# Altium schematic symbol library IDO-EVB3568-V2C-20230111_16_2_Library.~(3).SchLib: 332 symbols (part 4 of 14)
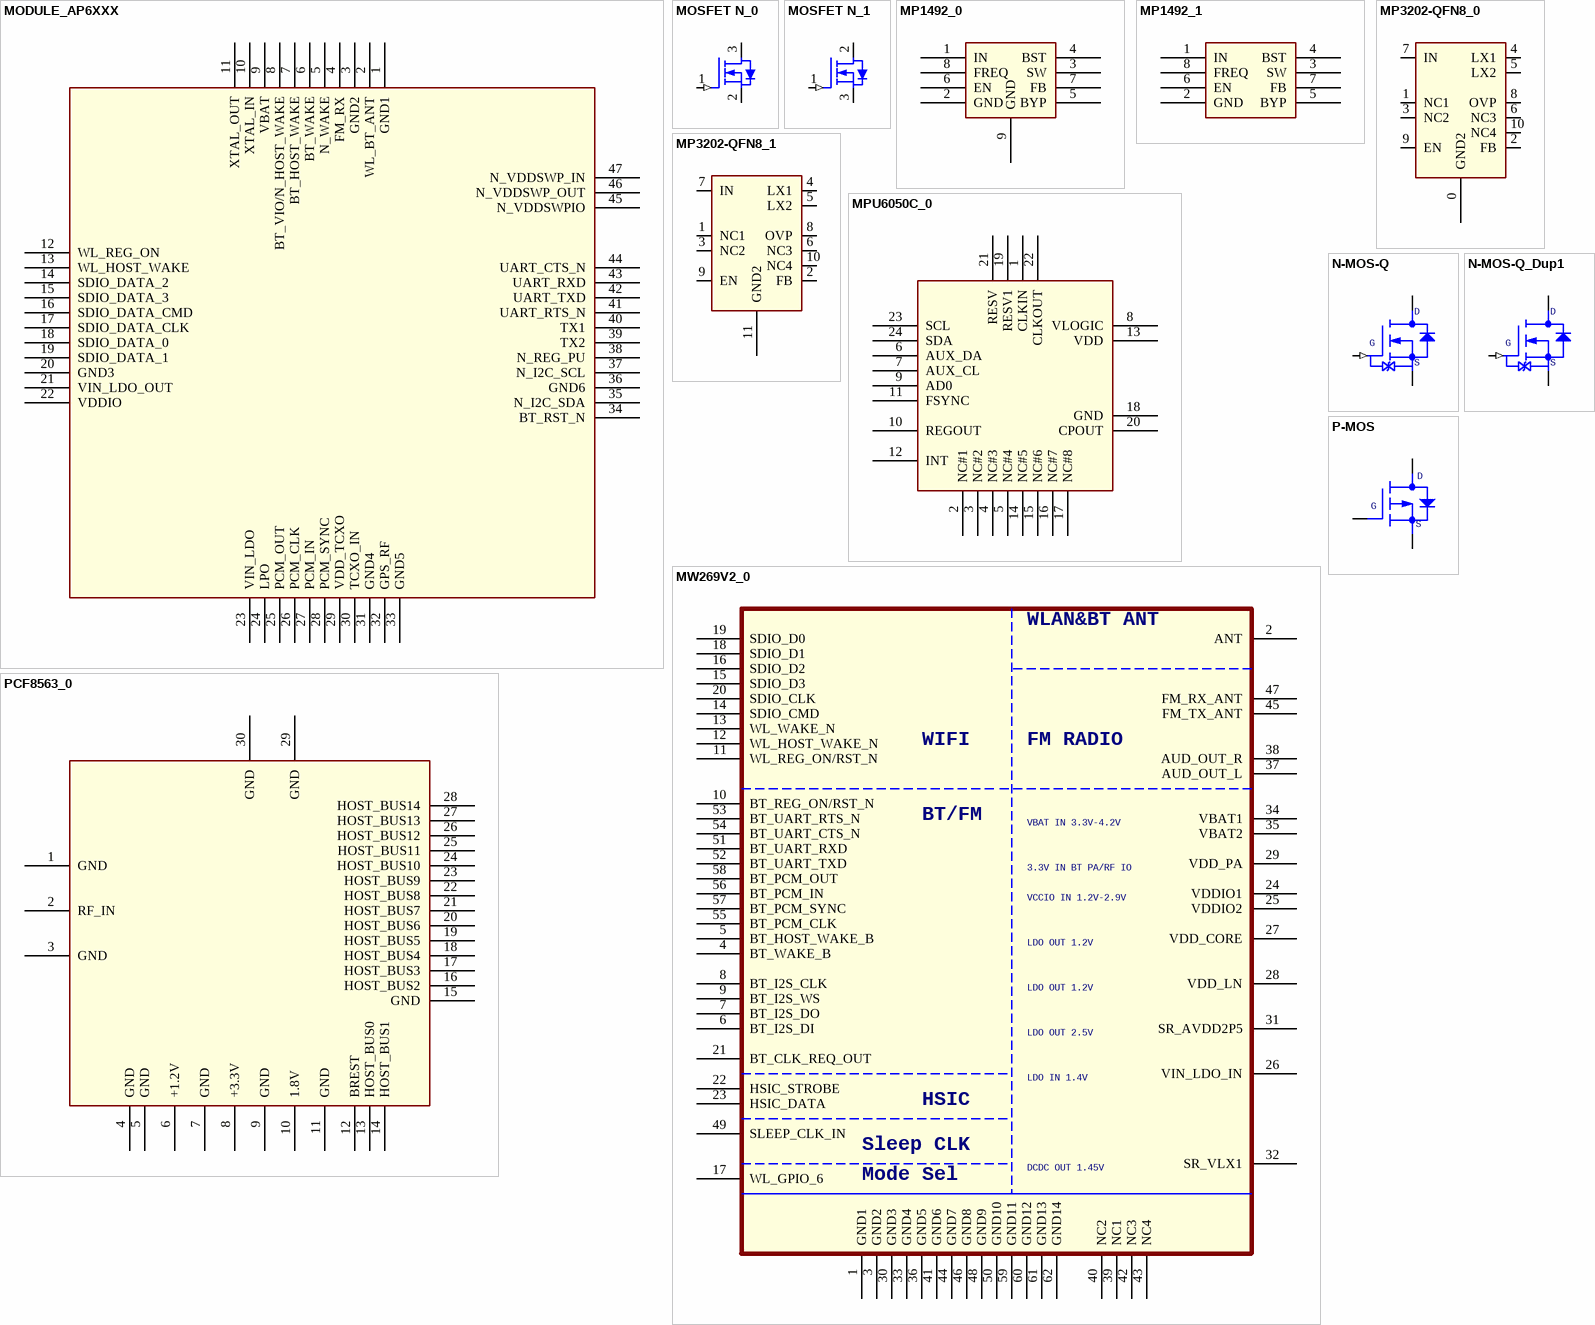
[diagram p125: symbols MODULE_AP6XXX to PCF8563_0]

## PCF8563_0
designator U?
Altium-Right: 240; Altium-Bottom: 230
footprint SOP-8
pins: 1 GND, 2 RF_IN, 3 GND, 4 GND, 5 GND, 6 +1.2V, 7 GND, 8 +3.3V, 9 GND, 10 1.8V, 11 GND, 12 BREST, 13 HOST_BUS0, 14 HOST_BUS1, 15 GND, 16 HOST_BUS2, 17 HOST_BUS3, 18 HOST_BUS4, 19 HOST_BUS5, 20 HOST_BUS6, 21 HOST_BUS7, 22 HOST_BUS8, 23 HOST_BUS9, 24 HOST_BUS10, 25 HOST_BUS11, 26 HOST_BUS12, 27 HOST_BUS13, 28 HOST_BUS14, 29 GND, 30 GND
1 alternate drawing of the same symbol

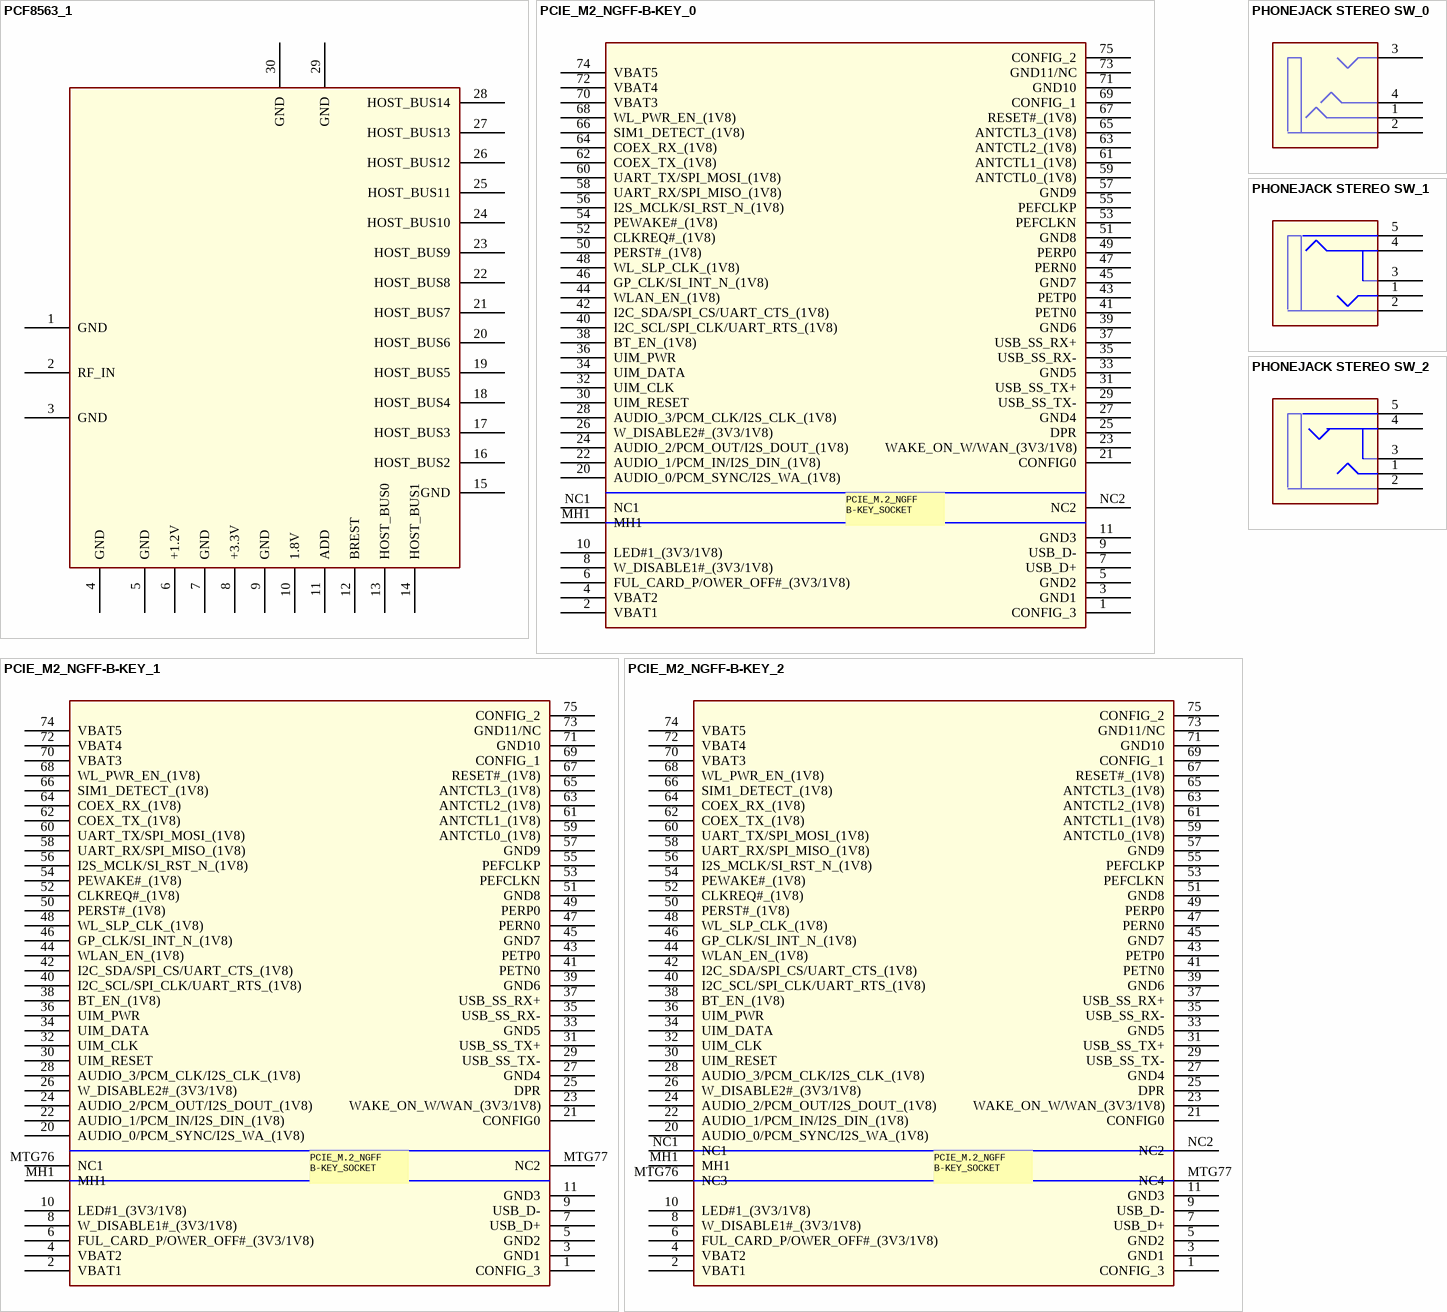
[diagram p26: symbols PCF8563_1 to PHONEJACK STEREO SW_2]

## PCF8563_1
designator U?
Altium-Right: 260; Altium-Bottom: 320
footprint SOP-8
pins: 1 GND, 2 RF_IN, 3 GND, 4 GND, 5 GND, 6 +1.2V, 7 GND, 8 +3.3V, 9 GND, 10 1.8V, 11 ADD, 12 BREST, 13 HOST_BUS0, 14 HOST_BUS1, 15 GND, 16 HOST_BUS2, 17 HOST_BUS3, 18 HOST_BUS4, 19 HOST_BUS5, 20 HOST_BUS6, 21 HOST_BUS7, 22 HOST_BUS8, 23 HOST_BUS9, 24 HOST_BUS10, 25 HOST_BUS11, 26 HOST_BUS12, 27 HOST_BUS13, 28 HOST_BUS14, 29 GND, 30 GND
1 alternate drawing of the same symbol

## PCIE_M2_NGFF-B-KEY_0
designator U?
Altium-Right: 320; Altium-Bottom: 390
pins: 1 CONFIG_3, 2 VBAT1, 3 GND1, 4 VBAT2, 5 GND2, 6 FUL_CARD_P/OWER_OFF#_(3V3/1V8), 7 USB_D+, 8 W_DISABLE1#_(3V3/1V8), 9 USB_D-, 10 LED#1_(3V3/1V8), 11 GND3, 20 AUDIO_0/PCM_SYNC/I2S_WA_(1V8), 21 CONFIG0, 22 AUDIO_1/PCM_IN/I2S_DIN_(1V8), 23 WAKE_ON_W/WAN_(3V3/1V8), 24 AUDIO_2/PCM_OUT/I2S_DOUT_(1V8), 25 DPR, 26 W_DISABLE2#_(3V3/1V8), 27 GND4, 28 AUDIO_3/PCM_CLK/I2S_CLK_(1V8), 29 USB_SS_TX-, 30 UIM_RESET, 31 USB_SS_TX+, 32 UIM_CLK, 33 GND5, 34 UIM_DATA, 35 USB_SS_RX-, 36 UIM_PWR, 37 USB_SS_RX+, 38 BT_EN_(1V8), 39 GND6, 40 I2C_SCL/SPI_CLK/UART_RTS_(1V8), 41 PETN0, 42 I2C_SDA/SPI_CS/UART_CTS_(1V8), 43 PETP0, 44 WLAN_EN_(1V8), 45 GND7, 46 GP_CLK/SI_INT_N_(1V8), 47 PERN0, 48 WL_SLP_CLK_(1V8), 49 PERP0, 50 PERST#_(1V8), 51 GND8, 52 CLKREQ#_(1V8), 53 PEFCLKN, 54 PEWAKE#_(1V8), 55 PEFCLKP, 56 I2S_MCLK/SI_RST_N_(1V8), 57 GND9, 58 UART_RX/SPI_MISO_(1V8), 59 ANTCTL0_(1V8), 60 UART_TX/SPI_MOSI_(1V8), 61 ANTCTL1_(1V8), 62 COEX_TX_(1V8), 63 ANTCTL2_(1V8), 64 COEX_RX_(1V8), 65 ANTCTL3_(1V8), 66 SIM1_DETECT_(1V8), 67 RESET#_(1V8), 68 WL_PWR_EN_(1V8), 69 CONFIG_1, 70 VBAT3, 71 GND10, 72 VBAT4, 73 GND11/NC, 74 VBAT5, 75 CONFIG_2, MH1, NC1, NC2

## PCIE_M2_NGFF-B-KEY_1
designator U?
Altium-Right: 320; Altium-Bottom: 390
pins: 1 CONFIG_3, 2 VBAT1, 3 GND1, 4 VBAT2, 5 GND2, 6 FUL_CARD_P/OWER_OFF#_(3V3/1V8), 7 USB_D+, 8 W_DISABLE1#_(3V3/1V8), 9 USB_D-, 10 LED#1_(3V3/1V8), 11 GND3, 20 AUDIO_0/PCM_SYNC/I2S_WA_(1V8), 21 CONFIG0, 22 AUDIO_1/PCM_IN/I2S_DIN_(1V8), 23 WAKE_ON_W/WAN_(3V3/1V8), 24 AUDIO_2/PCM_OUT/I2S_DOUT_(1V8), 25 DPR, 26 W_DISABLE2#_(3V3/1V8), 27 GND4, 28 AUDIO_3/PCM_CLK/I2S_CLK_(1V8), 29 USB_SS_TX-, 30 UIM_RESET, 31 USB_SS_TX+, 32 UIM_CLK, 33 GND5, 34 UIM_DATA, 35 USB_SS_RX-, 36 UIM_PWR, 37 USB_SS_RX+, 38 BT_EN_(1V8), 39 GND6, 40 I2C_SCL/SPI_CLK/UART_RTS_(1V8), 41 PETN0, 42 I2C_SDA/SPI_CS/UART_CTS_(1V8), 43 PETP0, 44 WLAN_EN_(1V8), 45 GND7, 46 GP_CLK/SI_INT_N_(1V8), 47 PERN0, 48 WL_SLP_CLK_(1V8), 49 PERP0, 50 PERST#_(1V8), 51 GND8, 52 CLKREQ#_(1V8), 53 PEFCLKN, 54 PEWAKE#_(1V8), 55 PEFCLKP, 56 I2S_MCLK/SI_RST_N_(1V8), 57 GND9, 58 UART_RX/SPI_MISO_(1V8), 59 ANTCTL0_(1V8), 60 UART_TX/SPI_MOSI_(1V8), 61 ANTCTL1_(1V8), 62 COEX_TX_(1V8), 63 ANTCTL2_(1V8), 64 COEX_RX_(1V8), 65 ANTCTL3_(1V8), 66 SIM1_DETECT_(1V8), 67 RESET#_(1V8), 68 WL_PWR_EN_(1V8), 69 CONFIG_1, 70 VBAT3, 71 GND10, 72 VBAT4, 73 GND11/NC, 74 VBAT5, 75 CONFIG_2, MH1, MTG76 NC1, MTG77 NC2

## PCIE_M2_NGFF-B-KEY_2
designator U?
Altium-Right: 320; Altium-Bottom: 390
pins: 1 CONFIG_3, 2 VBAT1, 3 GND1, 4 VBAT2, 5 GND2, 6 FUL_CARD_P/OWER_OFF#_(3V3/1V8), 7 USB_D+, 8 W_DISABLE1#_(3V3/1V8), 9 USB_D-, 10 LED#1_(3V3/1V8), 11 GND3, 20 AUDIO_0/PCM_SYNC/I2S_WA_(1V8), 21 CONFIG0, 22 AUDIO_1/PCM_IN/I2S_DIN_(1V8), 23 WAKE_ON_W/WAN_(3V3/1V8), 24 AUDIO_2/PCM_OUT/I2S_DOUT_(1V8), 25 DPR, 26 W_DISABLE2#_(3V3/1V8), 27 GND4, 28 AUDIO_3/PCM_CLK/I2S_CLK_(1V8), 29 USB_SS_TX-, 30 UIM_RESET, 31 USB_SS_TX+, 32 UIM_CLK, 33 GND5, 34 UIM_DATA, 35 USB_SS_RX-, 36 UIM_PWR, 37 USB_SS_RX+, 38 BT_EN_(1V8), 39 GND6, 40 I2C_SCL/SPI_CLK/UART_RTS_(1V8), 41 PETN0, 42 I2C_SDA/SPI_CS/UART_CTS_(1V8), 43 PETP0, 44 WLAN_EN_(1V8), 45 GND7, 46 GP_CLK/SI_INT_N_(1V8), 47 PERN0, 48 WL_SLP_CLK_(1V8), 49 PERP0, 50 PERST#_(1V8), 51 GND8, 52 CLKREQ#_(1V8), 53 PEFCLKN, 54 PEWAKE#_(1V8), 55 PEFCLKP, 56 I2S_MCLK/SI_RST_N_(1V8), 57 GND9, 58 UART_RX/SPI_MISO_(1V8), 59 ANTCTL0_(1V8), 60 UART_TX/SPI_MOSI_(1V8), 61 ANTCTL1_(1V8), 62 COEX_TX_(1V8), 63 ANTCTL2_(1V8), 64 COEX_RX_(1V8), 65 ANTCTL3_(1V8), 66 SIM1_DETECT_(1V8), 67 RESET#_(1V8), 68 WL_PWR_EN_(1V8), 69 CONFIG_1, 70 VBAT3, 71 GND10, 72 VBAT4, 73 GND11/NC, 74 VBAT5, 75 CONFIG_2, MH1, MTG76 NC3, MTG77 NC4, NC1, NC2

## PHONEJACK STEREO SW_0
designator J?
Altium-Right: 70
pins: 1 HP, 2 COM, 3 L, 4 R

## PHONEJACK STEREO SW_1
designator J?
Altium-Right: 70
footprint PHONE-ST-0166MT-050
pins: 1 R, 2 COM, 3 HP, 4 L, 5

## PHONEJACK STEREO SW_2
designator J?
Altium-Right: 70
footprint PHONE-ST-0166MT-050
pins: 1 R, 2 COM, 3 HP, 4 L, 5

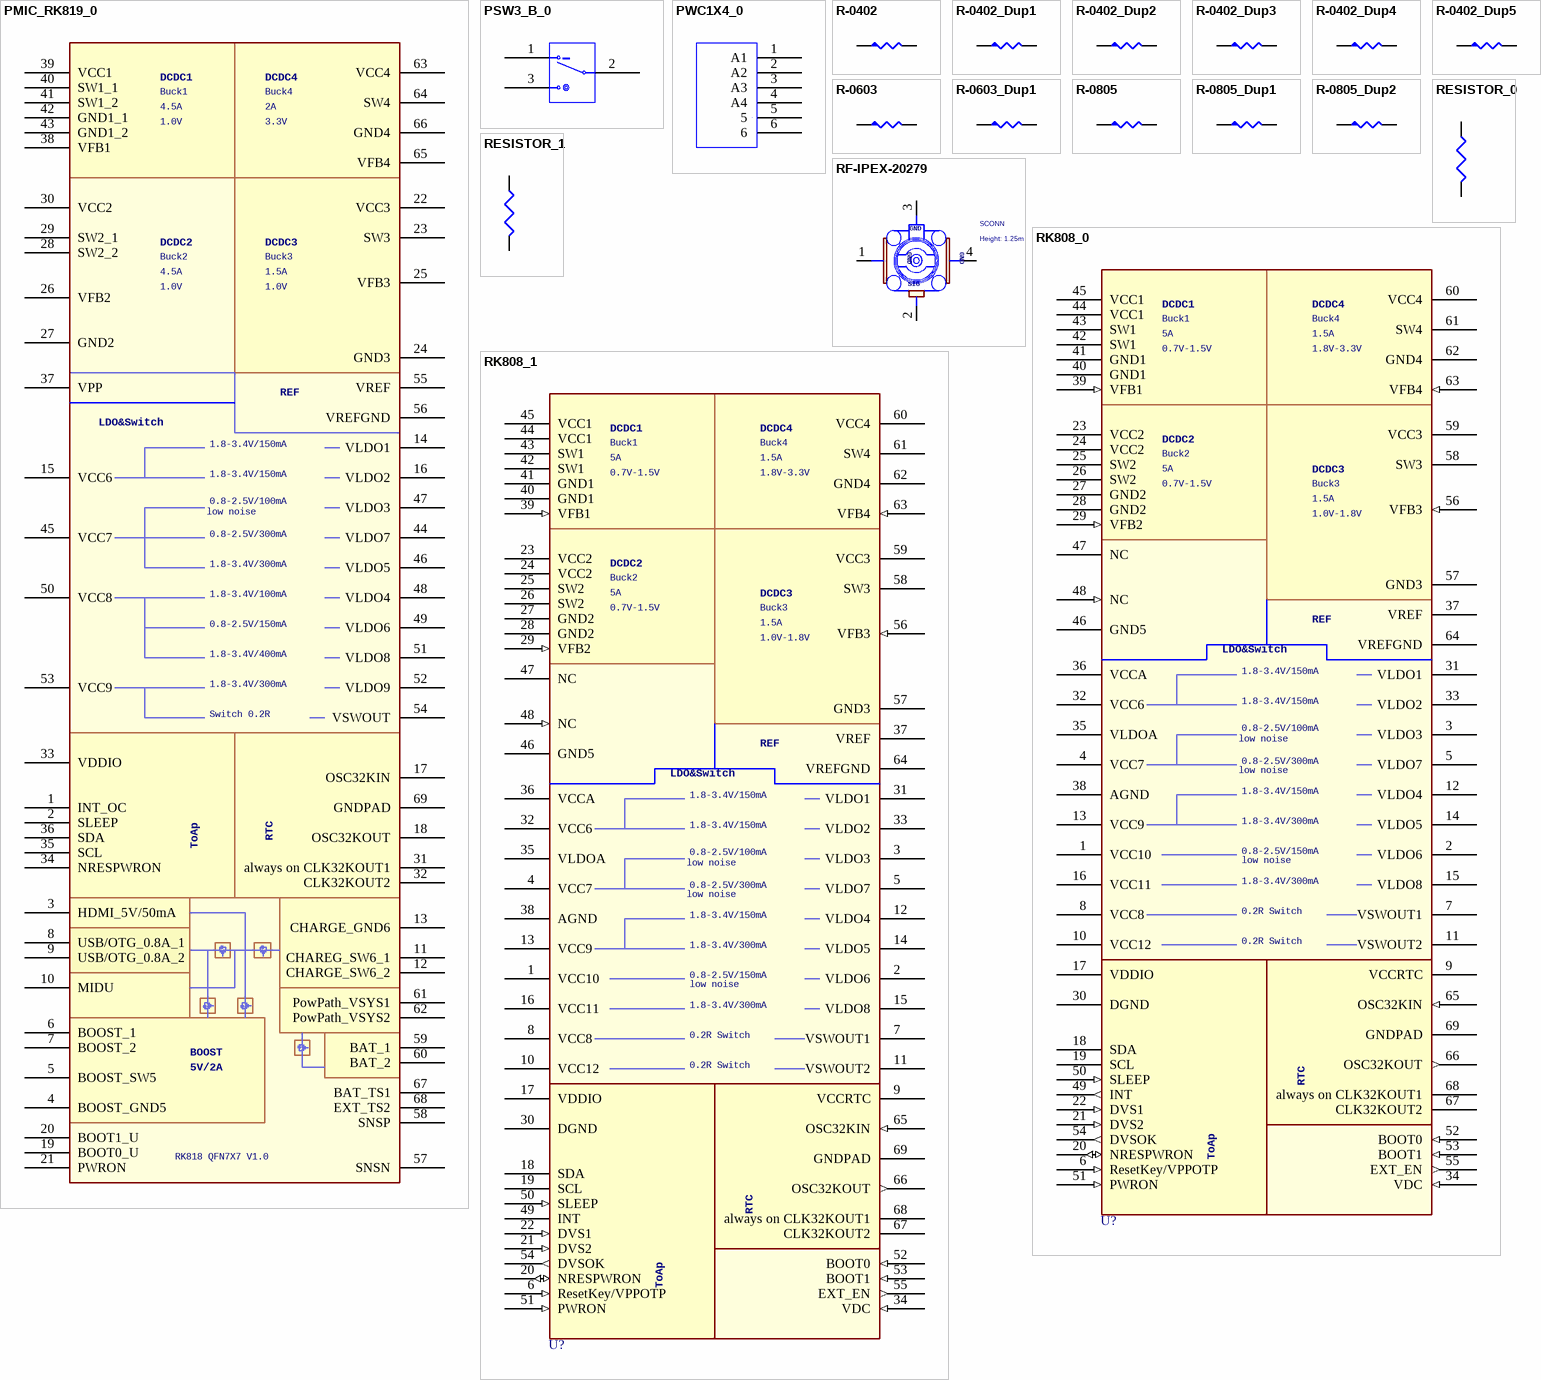
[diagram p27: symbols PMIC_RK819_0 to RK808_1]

## PMIC_RK819_0
designator U?
Altium-Right: 220; Altium-Bottom: 760
footprint QFN68
pins: 1 INT_OC, 2 SLEEP, 3 HDMI_5V/50mA, 4 BOOST_GND5, 5 BOOST_SW5, 6 BOOST_1, 7 BOOST_2, 8 USB/OTG_0.8A_1, 9 USB/OTG_0.8A_2, 10 MIDU, 11 CHAREG_SW6_1, 12 CHARGE_SW6_2, 13 CHARGE_GND6, 14 VLDO1, 15 VCC6, 16 VLDO2, 17 OSC32KIN, 18 OSC32KOUT, 19 BOOT0_U, 20 BOOT1_U, 21 PWRON, 22 VCC3, 23 SW3, 24 GND3, 25 VFB3, 26 VFB2, 27 GND2, 28 SW2_2, 29 SW2_1, 30 VCC2, 31 always on CLK32KOUT1, 32 CLK32KOUT2, 33 VDDIO, 34 NRESPWRON, 35 SCL, 36 SDA, 37 VPP, 38 VFB1, 39 VCC1, 40 SW1_1, 41 SW1_2, 42 GND1_1, 43 GND1_2, 44 VLDO7, 45 VCC7, 46 VLDO5, 47 VLDO3, 48 VLDO4, 49 VLDO6, 50 VCC8, 51 VLDO8, 52 VLDO9, 53 VCC9, 54 VSWOUT, 55 VREF, 56 VREFGND, 57 SNSN, 58 SNSP, 59 BAT_1, 60 BAT_2, 61 PowPath_VSYS1, 62 PowPath_VSYS2, 63 VCC4, 64 SW4, 65 VFB4, 66 GND4, 67 BAT_TS1, 68 EXT_TS2, 69 GNDPAD

## PSW3_B_0
designator S?, comment PSW3_B  (value not drawn)
PARTS: 1; DEVICE: BR-11C-11P6; LEVEL: STD; OriginalSymbolOrigin: (20,50); Altium-Right: 30; Altium-Bottom: 40
pins: 1 P1, 2 P2, 3 P3

## PWC1X4_0
designator J?, comment PWC1X4  (value not drawn)
PARTS: 1; DEVICE: HEAD1X4; LEVEL: STD; PKG_TYPE: 4; OriginalSymbolOrigin: (0,70); Altium-Right: 40; Altium-Bottom: 70
pins: 1 A1, 2 A2, 3 A3, 4 A4, 5, 6

## R-0402
designator R?
Altium-Right: 20
pins: 1, 2

## R-0402_Dup1
designator R?
Altium-Right: 20
pins: 1, 2

## R-0402_Dup2
designator R?
Altium-Right: 20
pins: 1, 2

## R-0402_Dup3
designator R?
Altium-Right: 20
pins: 1, 2

## R-0402_Dup4
designator R?
Altium-Right: 20
pins: 1, 2

## R-0402_Dup5
designator R?
Altium-Right: 20
pins: 1, 2

## R-0603
designator R?
Altium-Right: 20
pins: 1, 2

## R-0603_Dup1
designator R?
Altium-Right: 20
pins: 1, 2

## R-0805
designator R?
Altium-Right: 20
pins: 1, 2

## R-0805_Dup1
designator R?
Altium-Right: 20
pins: 1, 2

## R-0805_Dup2
designator R?
Altium-Right: 20
pins: 1, 2

## RESISTOR_0
designator R?
Altium-Right: 20; Altium-Bottom: 30
pins: 1, 2

## RESISTOR_1
designator R?
Altium-Right: 20; Altium-Bottom: 30
pins: 1, 2

## RF-IPEX-20279
designator IPEX?  Material: SCONN  Height: 1.25mm
SMD micro Coaxial Connector Receptacle vertial; Pack_Type: MHF-20279; Altium-Right: 60
pins: 1 GND1, 2 SIG, 3 GND2, 4 GND3

## RK808_0
designator U?  (value not drawn)
Altium-Right: 220; Altium-Bottom: 630
pins: 1 VCC10 (power), 2 VLDO6 (power), 3 VLDO3 (power), 4 VCC7 (power), 5 VLDO7 (power), 6 ResetKey/VPPOTP (in), 7 VSWOUT1 (power), 8 VCC8 (power), 9 VCCRTC (power), 10 VCC12 (power), 11 VSWOUT2 (power), 12 VLDO4 (power), 13 VCC9 (power), 14 VLDO5 (power), 15 VLDO8 (power), 16 VCC11 (power), 17 VDDIO (power), 18 SDA (oc), 19 SCL (oc), 20 NRESPWRON (io), 21 DVS2 (in), 22 DVS1 (in), 23 VCC2 (power), 24 VCC2 (power), 25 SW2 (power), 26 SW2 (power), 27 GND2 (power), 28 GND2 (power), 29 VFB2 (in), 30 DGND (power), 31 VLDO1 (power), 32 VCC6 (power), 33 VLDO2 (power), 34 VDC (in), 35 VLDOA (power), 36 VCCA (power), 37 VREF (power), 38 AGND (power), 39 VFB1 (in), 40 GND1 (power), 41 GND1 (power), 42 SW1 (power), 43 SW1 (power), 44 VCC1 (power), 45 VCC1 (power), 46 GND5 (power), 47 NC (hiz), 48 NC (in), 49 INT (out), 50 SLEEP (in), 51 PWRON (in), 52 BOOT0 (in), 53 BOOT1 (in), 54 DVSOK (out), 55 EXT_EN (out), 56 VFB3 (in), 57 GND3 (power), 58 SW3 (power), 59 VCC3 (power), 60 VCC4 (power), 61 SW4 (power), 62 GND4 (power), 63 VFB4 (in), 64 VREFGND (power), 65 OSC32KIN (in), 66 OSC32KOUT (out), 67 CLK32KOUT2 (oc), 68 always on CLK32KOUT1 (oc), 69 GNDPAD (power)

## RK808_1
designator U?  (value not drawn)
Altium-Right: 220; Altium-Bottom: 630
pins: 1 VCC10 (power), 2 VLDO6 (power), 3 VLDO3 (power), 4 VCC7 (power), 5 VLDO7 (power), 6 ResetKey/VPPOTP (in), 7 VSWOUT1 (power), 8 VCC8 (power), 9 VCCRTC (power), 10 VCC12 (power), 11 VSWOUT2 (power), 12 VLDO4 (power), 13 VCC9 (power), 14 VLDO5 (power), 15 VLDO8 (power), 16 VCC11 (power), 17 VDDIO (power), 18 SDA (oc), 19 SCL (oc), 20 NRESPWRON (io), 21 DVS2 (in), 22 DVS1 (in), 23 VCC2 (power), 24 VCC2 (power), 25 SW2 (power), 26 SW2 (power), 27 GND2 (power), 28 GND2 (power), 29 VFB2 (in), 30 DGND (power), 31 VLDO1 (power), 32 VCC6 (power), 33 VLDO2 (power), 34 VDC (in), 35 VLDOA (power), 36 VCCA (power), 37 VREF (power), 38 AGND (power), 39 VFB1 (in), 40 GND1 (power), 41 GND1 (power), 42 SW1 (power), 43 SW1 (power), 44 VCC1 (power), 45 VCC1 (power), 46 GND5 (power), 47 NC (hiz), 48 NC (in), 49 INT, 50 SLEEP (in), 51 PWRON (in), 52 BOOT0 (in), 53 BOOT1 (in), 54 DVSOK (out), 55 EXT_EN (out), 56 VFB3 (in), 57 GND3 (power), 58 SW3 (power), 59 VCC3 (power), 60 VCC4 (power), 61 SW4 (power), 62 GND4 (power), 63 VFB4 (in), 64 VREFGND (power), 65 OSC32KIN (in), 66 OSC32KOUT (out), 67 CLK32KOUT2 (oc), 68 always on CLK32KOUT1 (oc), 69 GNDPAD (power)

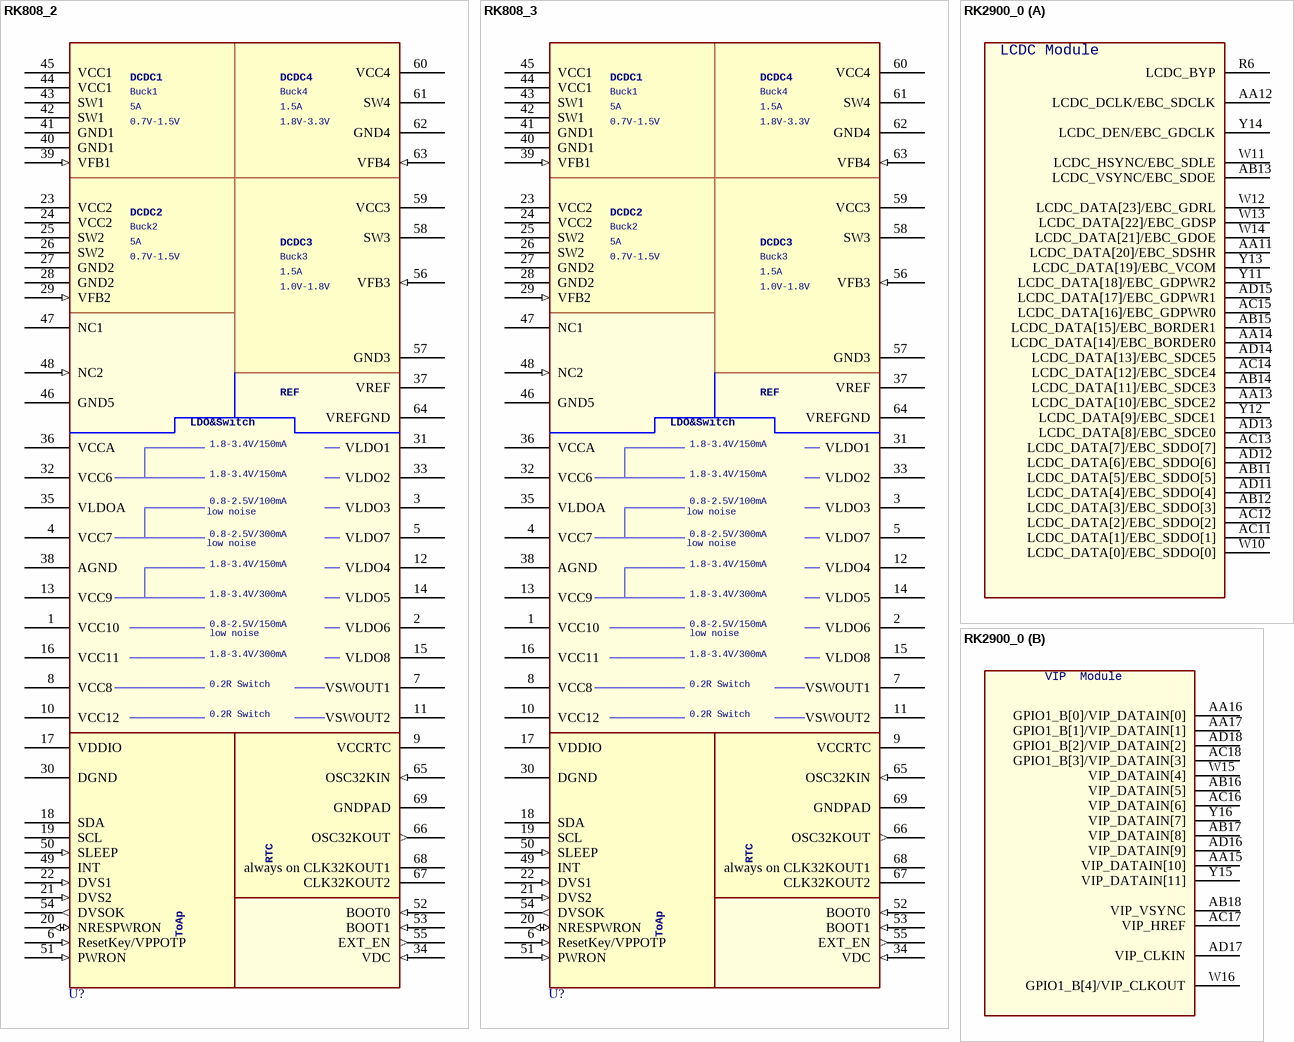
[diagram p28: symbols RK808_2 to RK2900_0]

## RK808_2
designator U?  (value not drawn)
Altium-Right: 220; Altium-Bottom: 630
pins: 1 VCC10 (power), 2 VLDO6 (power), 3 VLDO3 (power), 4 VCC7 (power), 5 VLDO7 (power), 6 ResetKey/VPPOTP (in), 7 VSWOUT1 (power), 8 VCC8 (power), 9 VCCRTC (power), 10 VCC12 (power), 11 VSWOUT2 (power), 12 VLDO4 (power), 13 VCC9 (power), 14 VLDO5 (power), 15 VLDO8 (power), 16 VCC11 (power), 17 VDDIO (power), 18 SDA (oc), 19 SCL (oc), 20 NRESPWRON (io), 21 DVS2 (in), 22 DVS1 (in), 23 VCC2 (power), 24 VCC2 (power), 25 SW2 (power), 26 SW2 (power), 27 GND2 (power), 28 GND2 (power), 29 VFB2 (in), 30 DGND (power), 31 VLDO1 (power), 32 VCC6 (power), 33 VLDO2 (power), 34 VDC (in), 35 VLDOA (power), 36 VCCA (power), 37 VREF (power), 38 AGND (power), 39 VFB1 (in), 40 GND1 (power), 41 GND1 (power), 42 SW1 (power), 43 SW1 (power), 44 VCC1 (power), 45 VCC1 (power), 46 GND5 (power), 47 NC1 (hiz), 48 NC2 (in), 49 INT, 50 SLEEP (in), 51 PWRON (in), 52 BOOT0 (in), 53 BOOT1 (in), 54 DVSOK (out), 55 EXT_EN (out), 56 VFB3 (in), 57 GND3 (power), 58 SW3 (power), 59 VCC3 (power), 60 VCC4 (power), 61 SW4 (power), 62 GND4 (power), 63 VFB4 (in), 64 VREFGND (power), 65 OSC32KIN (in), 66 OSC32KOUT (out), 67 CLK32KOUT2 (oc), 68 always on CLK32KOUT1 (oc), 69 GNDPAD (power)

## RK808_3
designator U?  (value not drawn)
Altium-Right: 220; Altium-Bottom: 630
pins: 1 VCC10 (power), 2 VLDO6 (power), 3 VLDO3 (power), 4 VCC7 (power), 5 VLDO7 (power), 6 ResetKey/VPPOTP (in), 7 VSWOUT1 (power), 8 VCC8 (power), 9 VCCRTC (power), 10 VCC12 (power), 11 VSWOUT2 (power), 12 VLDO4 (power), 13 VCC9 (power), 14 VLDO5 (power), 15 VLDO8 (power), 16 VCC11 (power), 17 VDDIO (power), 18 SDA (oc), 19 SCL (oc), 20 NRESPWRON (io), 21 DVS2 (in), 22 DVS1 (in), 23 VCC2 (power), 24 VCC2 (power), 25 SW2 (power), 26 SW2 (power), 27 GND2 (power), 28 GND2 (power), 29 VFB2 (in), 30 DGND (power), 31 VLDO1 (power), 32 VCC6 (power), 33 VLDO2 (power), 34 VDC (in), 35 VLDOA (power), 36 VCCA (power), 37 VREF (power), 38 AGND (power), 39 VFB1 (in), 40 GND1 (power), 41 GND1 (power), 42 SW1 (power), 43 SW1 (power), 44 VCC1 (power), 45 VCC1 (power), 46 GND5 (power), 47 NC1 (hiz), 48 NC2 (in), 49 INT, 50 SLEEP (in), 51 PWRON (in), 52 BOOT0 (in), 53 BOOT1 (in), 54 DVSOK (out), 55 EXT_EN (out), 56 VFB3 (in), 57 GND3 (power), 58 SW3 (power), 59 VCC3 (power), 60 VCC4 (power), 61 SW4 (power), 62 GND4 (power), 63 VFB4 (in), 64 VREFGND (power), 65 OSC32KIN (in), 66 OSC32KOUT (out), 67 CLK32KOUT2 (oc), 68 always on CLK32KOUT1 (oc), 69 GNDPAD (power)

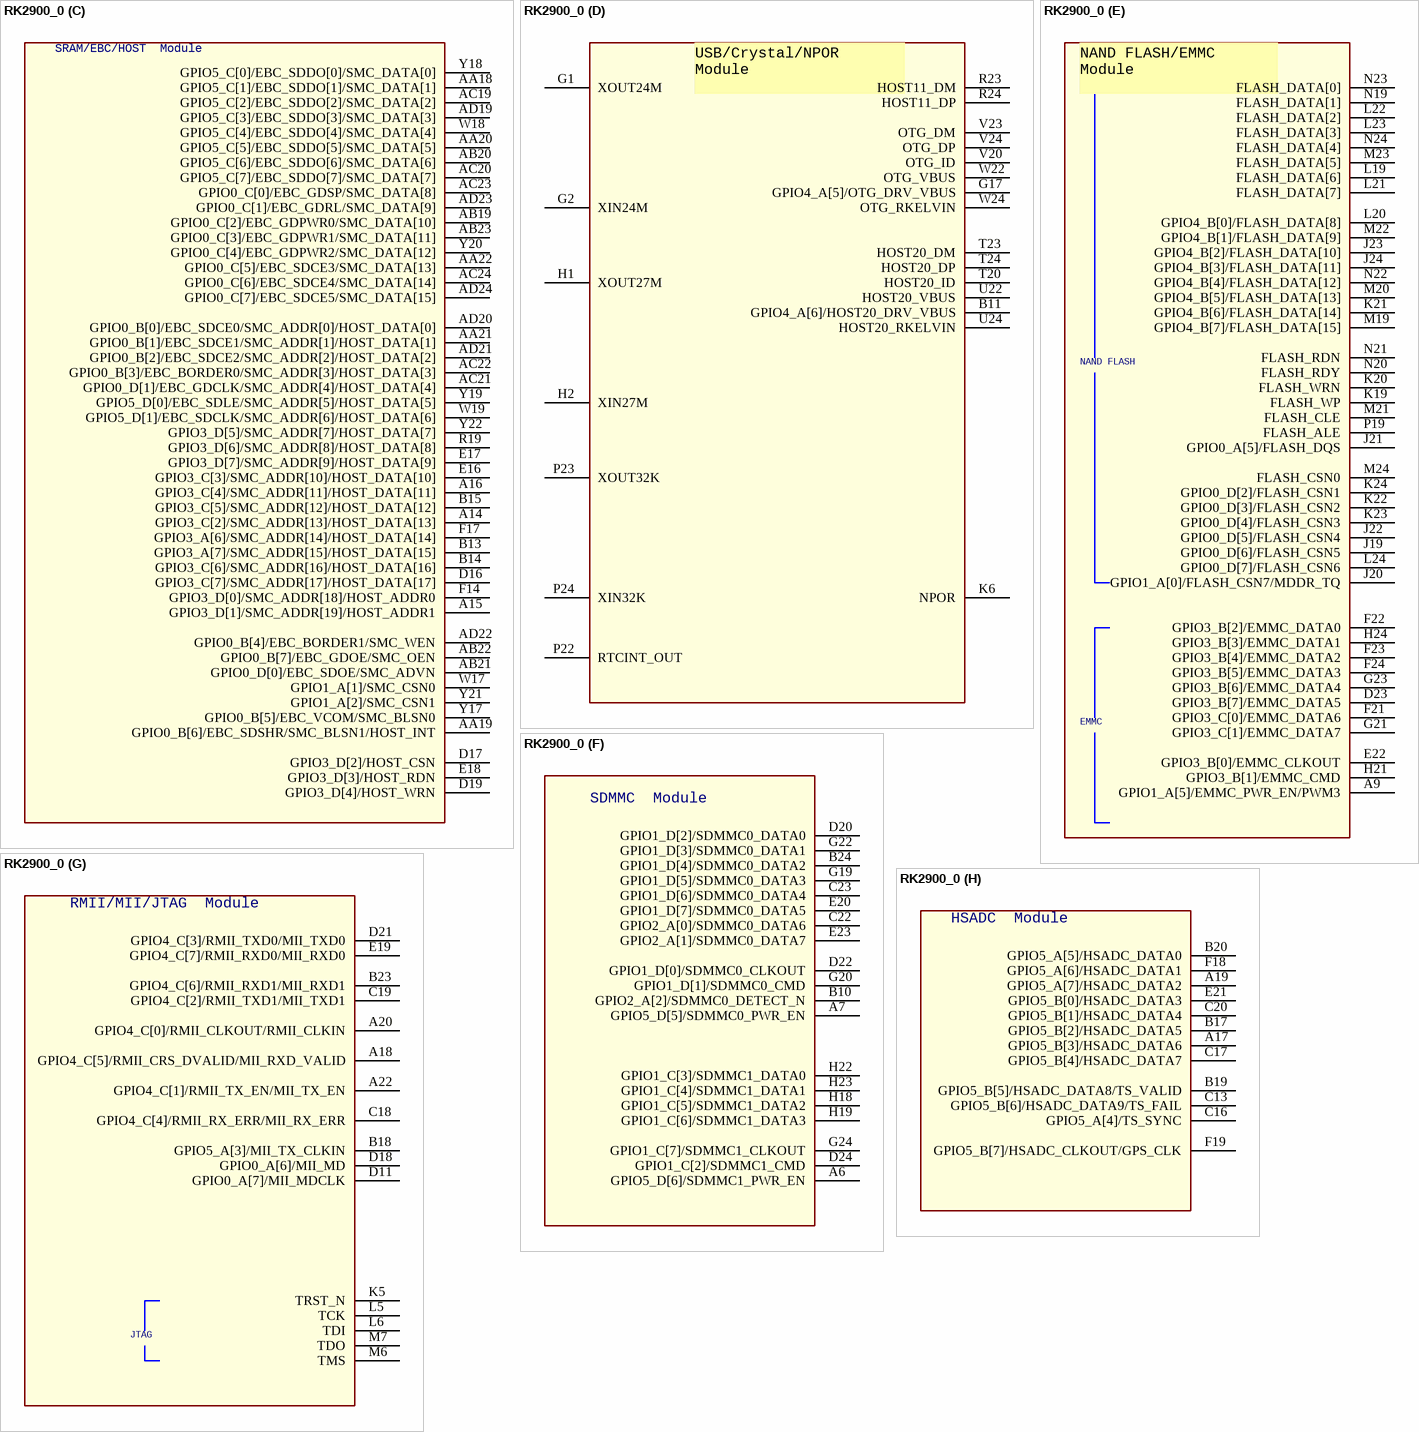
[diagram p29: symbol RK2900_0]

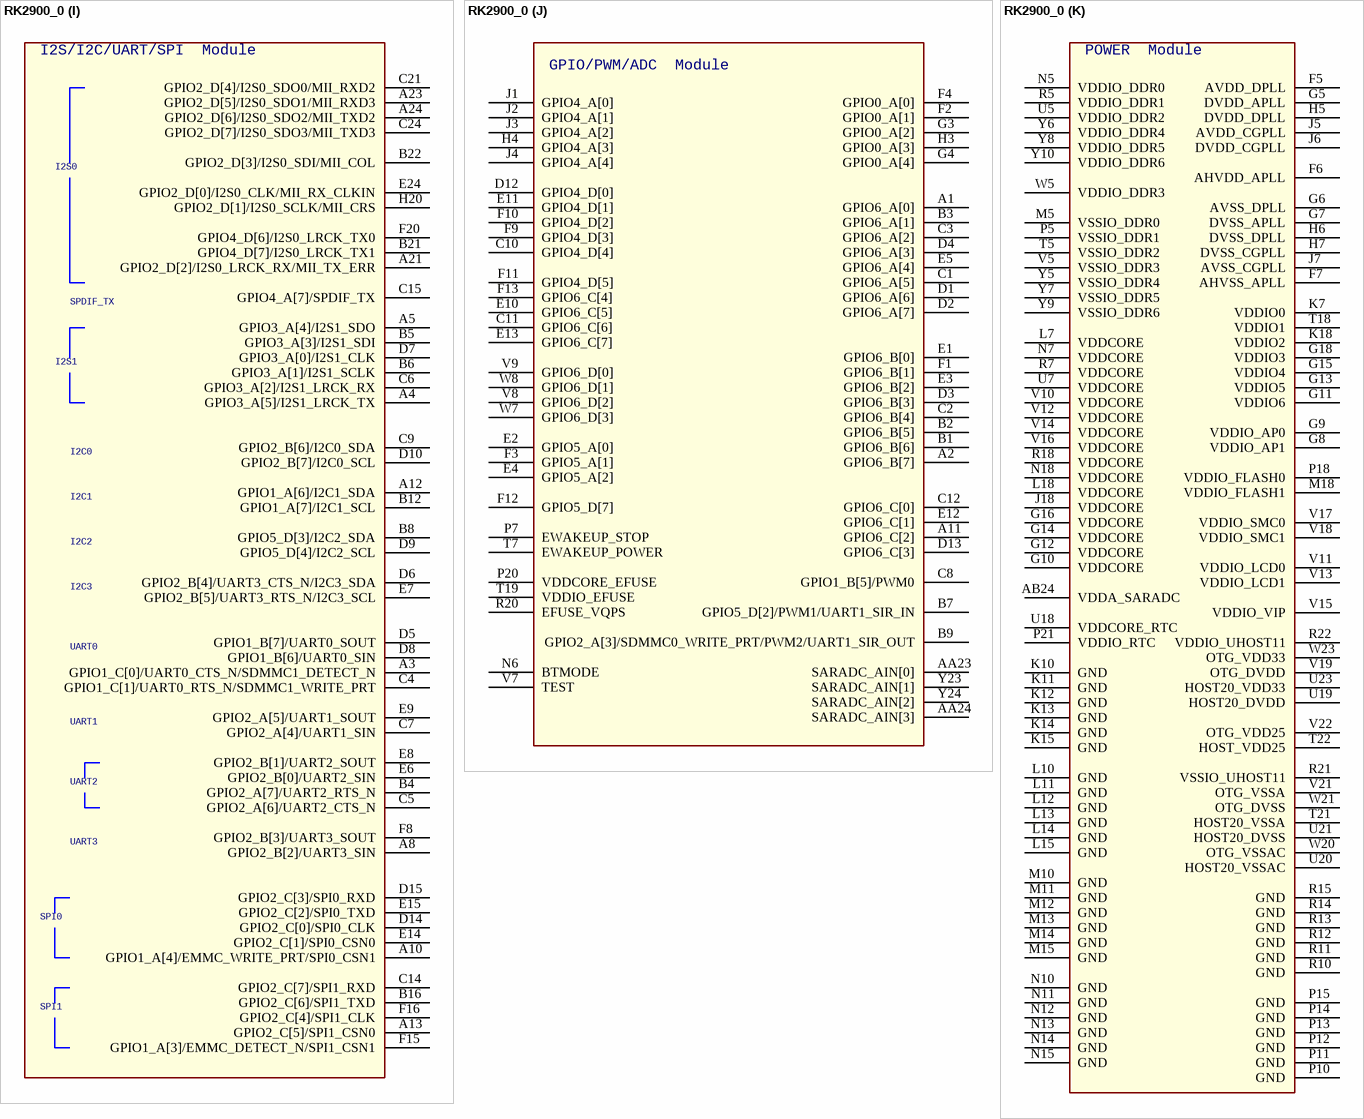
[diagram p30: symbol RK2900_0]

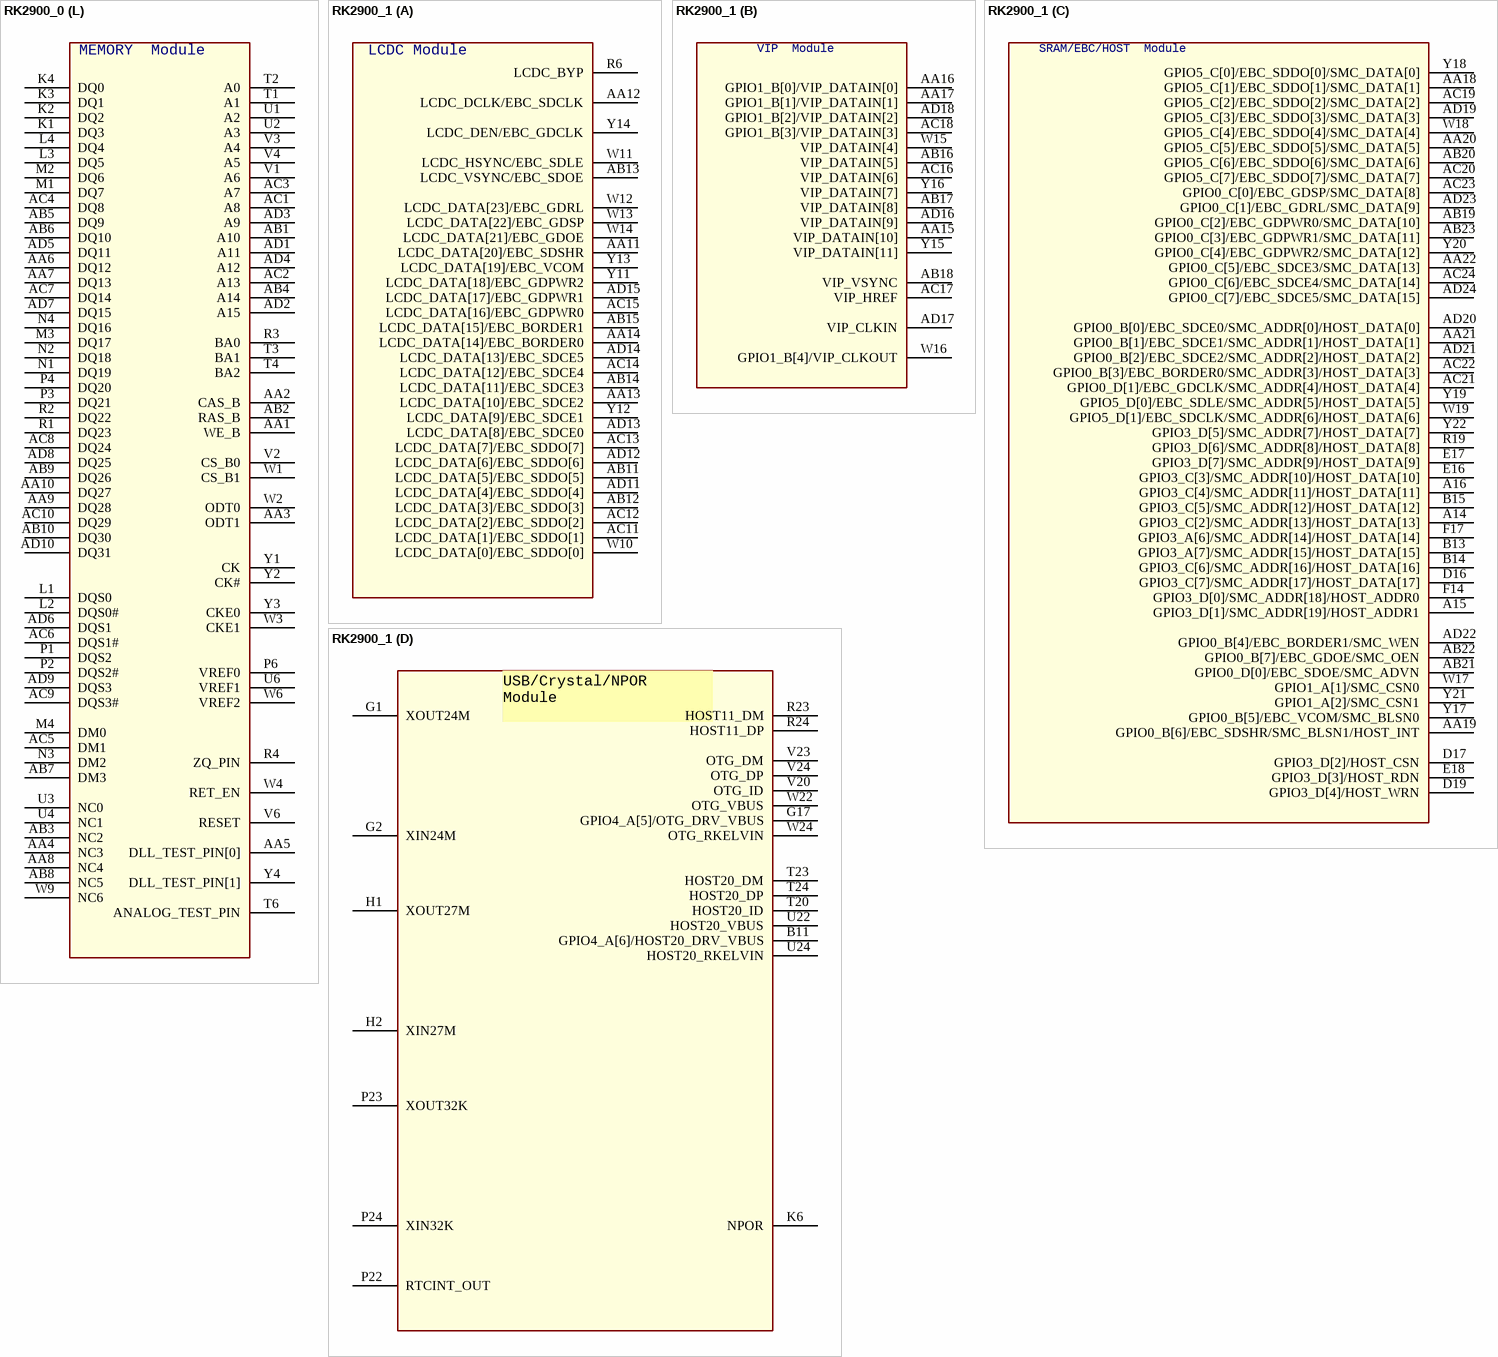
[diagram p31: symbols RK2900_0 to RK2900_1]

## RK2900_0
designator U?
Altium-Right: 120; Altium-Bottom: 610; Altium-Right1: 150; Altium-Bottom1: 700; Altium-Right2: 260; Altium-Bottom2: 469; Altium-Right3: 240; Altium-Bottom3: 690; Altium-Right4: 180; Altium-Bottom4: 200; Altium-Right5: 220; Altium-Bottom5: 340; Altium-Bottom6: 300; Altium-Right7: 190; Altium-Bottom7: 530; Altium-Right8: 250; Altium-Bottom8: 440; Altium-Right9: 280; Altium-Bottom9: 520; Altium-Right10: 140; Altium-Bottom10: 230; Altium-Right11: 160; Altium-Bottom11: 370
footprint BGA512
part A pins: AA11 LCDC_DATA[20]/EBC_SDSHR, AA12 LCDC_DCLK/EBC_SDCLK, AA13 LCDC_DATA[10]/EBC_SDCE2, AA14 LCDC_DATA[14]/EBC_BORDER0, AB11 LCDC_DATA[5]/EBC_SDDO[5], AB12 LCDC_DATA[3]/EBC_SDDO[3], AB13 LCDC_VSYNC/EBC_SDOE, AB14 LCDC_DATA[11]/EBC_SDCE3, AB15 LCDC_DATA[15]/EBC_BORDER1, AC11 LCDC_DATA[1]/EBC_SDDO[1], AC12 LCDC_DATA[2]/EBC_SDDO[2], AC13 LCDC_DATA[7]/EBC_SDDO[7], AC14 LCDC_DATA[12]/EBC_SDCE4, AC15 LCDC_DATA[16]/EBC_GDPWR0, AD11 LCDC_DATA[4]/EBC_SDDO[4], AD12 LCDC_DATA[6]/EBC_SDDO[6], AD13 LCDC_DATA[8]/EBC_SDCE0, AD14 LCDC_DATA[13]/EBC_SDCE5, AD15 LCDC_DATA[17]/EBC_GDPWR1, R6 LCDC_BYP, W10 LCDC_DATA[0]/EBC_SDDO[0], W11 LCDC_HSYNC/EBC_SDLE, W12 LCDC_DATA[23]/EBC_GDRL, W13 LCDC_DATA[22]/EBC_GDSP, W14 LCDC_DATA[21]/EBC_GDOE, Y11 LCDC_DATA[18]/EBC_GDPWR2, Y12 LCDC_DATA[9]/EBC_SDCE1, Y13 LCDC_DATA[19]/EBC_VCOM, Y14 LCDC_DEN/EBC_GDCLK
part B pins: AA15 VIP_DATAIN[10], AA16 GPIO1_B[0]/VIP_DATAIN[0], AA17 GPIO1_B[1]/VIP_DATAIN[1], AB16 VIP_DATAIN[5], AB17 VIP_DATAIN[8], AB18 VIP_VSYNC, AC16 VIP_DATAIN[6], AC17 VIP_HREF, AC18 GPIO1_B[3]/VIP_DATAIN[3], AD16 VIP_DATAIN[9], AD17 VIP_CLKIN, AD18 GPIO1_B[2]/VIP_DATAIN[2], W15 VIP_DATAIN[4], W16 GPIO1_B[4]/VIP_CLKOUT, Y15 VIP_DATAIN[11], Y16 VIP_DATAIN[7]
part C pins: A14 GPIO3_C[2]/SMC_ADDR[13]/HOST_DATA[13], A15 GPIO3_D[1]/SMC_ADDR[19]/HOST_ADDR1, A16 GPIO3_C[4]/SMC_ADDR[11]/HOST_DATA[11], AA18 GPIO5_C[1]/EBC_SDDO[1]/SMC_DATA[1], AA19 GPIO0_B[6]/EBC_SDSHR/SMC_BLSN1/HOST_INT, AA20 GPIO5_C[5]/EBC_SDDO[5]/SMC_DATA[5], AA21 GPIO0_B[1]/EBC_SDCE1/SMC_ADDR[1]/HOST_DATA[1], AA22 GPIO0_C[5]/EBC_SDCE3/SMC_DATA[13], AB19 GPIO0_C[2]/EBC_GDPWR0/SMC_DATA[10], AB20 GPIO5_C[6]/EBC_SDDO[6]/SMC_DATA[6], AB21 GPIO0_D[0]/EBC_SDOE/SMC_ADVN, AB22 GPIO0_B[7]/EBC_GDOE/SMC_OEN, AB23 GPIO0_C[3]/EBC_GDPWR1/SMC_DATA[11], AC19 GPIO5_C[2]/EBC_SDDO[2]/SMC_DATA[2], AC20 GPIO5_C[7]/EBC_SDDO[7]/SMC_DATA[7], AC21 GPIO0_D[1]/EBC_GDCLK/SMC_ADDR[4]/HOST_DATA[4], AC22 GPIO0_B[3]/EBC_BORDER0/SMC_ADDR[3]/HOST_DATA[3], AC23 GPIO0_C[0]/EBC_GDSP/SMC_DATA[8], AC24 GPIO0_C[6]/EBC_SDCE4/SMC_DATA[14], AD19 GPIO5_C[3]/EBC_SDDO[3]/SMC_DATA[3], AD20 GPIO0_B[0]/EBC_SDCE0/SMC_ADDR[0]/HOST_DATA[0], AD21 GPIO0_B[2]/EBC_SDCE2/SMC_ADDR[2]/HOST_DATA[2], AD22 GPIO0_B[4]/EBC_BORDER1/SMC_WEN, AD23 GPIO0_C[1]/EBC_GDRL/SMC_DATA[9], AD24 GPIO0_C[7]/EBC_SDCE5/SMC_DATA[15], B13 GPIO3_A[7]/SMC_ADDR[15]/HOST_DATA[15], B14 GPIO3_C[6]/SMC_ADDR[16]/HOST_DATA[16], B15 GPIO3_C[5]/SMC_ADDR[12]/HOST_DATA[12], D16 GPIO3_C[7]/SMC_ADDR[17]/HOST_DATA[17], D17 GPIO3_D[2]/HOST_CSN, D19 GPIO3_D[4]/HOST_WRN, E16 GPIO3_C[3]/SMC_ADDR[10]/HOST_DATA[10], E17 GPIO3_D[7]/SMC_ADDR[9]/HOST_DATA[9], E18 GPIO3_D[3]/HOST_RDN, F14 GPIO3_D[0]/SMC_ADDR[18]/HOST_ADDR0, F17 GPIO3_A[6]/SMC_ADDR[14]/HOST_DATA[14], R19 GPIO3_D[6]/SMC_ADDR[8]/HOST_DATA[8], W17 GPIO1_A[1]/SMC_CSN0, W18 GPIO5_C[4]/EBC_SDDO[4]/SMC_DATA[4], W19 GPIO5_D[1]/EBC_SDCLK/SMC_ADDR[6]/HOST_DATA[6], Y17 GPIO0_B[5]/EBC_VCOM/SMC_BLSN0, Y18 GPIO5_C[0]/EBC_SDDO[0]/SMC_DATA[0], Y19 GPIO5_D[0]/EBC_SDLE/SMC_ADDR[5]/HOST_DATA[5], Y20 GPIO0_C[4]/EBC_GDPWR2/SMC_DATA[12], Y21 GPIO1_A[2]/SMC_CSN1, Y22 GPIO3_D[5]/SMC_ADDR[7]/HOST_DATA[7]
part D pins: B11 GPIO4_A[6]/HOST20_DRV_VBUS, G1 XOUT24M, G2 XIN24M, G17 GPIO4_A[5]/OTG_DRV_VBUS, H1 XOUT27M, H2 XIN27M, K6 NPOR, P22 RTCINT_OUT, P23 XOUT32K, P24 XIN32K, R23 HOST11_DM, R24 HOST11_DP, T20 HOST20_ID, T23 HOST20_DM, T24 HOST20_DP, U22 HOST20_VBUS, U24 HOST20_RKELVIN, V20 OTG_ID, V23 OTG_DM, V24 OTG_DP, W22 OTG_VBUS, W24 OTG_RKELVIN
part E pins: A9 GPIO1_A[5]/EMMC_PWR_EN/PWM3, D23 GPIO3_B[7]/EMMC_DATA5, E22 GPIO3_B[0]/EMMC_CLKOUT, F21 GPIO3_C[0]/EMMC_DATA6, F22 GPIO3_B[2]/EMMC_DATA0, F23 GPIO3_B[4]/EMMC_DATA2, F24 GPIO3_B[5]/EMMC_DATA3, G21 GPIO3_C[1]/EMMC_DATA7, G23 GPIO3_B[6]/EMMC_DATA4, H21 GPIO3_B[1]/EMMC_CMD, H24 GPIO3_B[3]/EMMC_DATA1, J19 GPIO0_D[6]/FLASH_CSN5, J20 GPIO1_A[0]/FLASH_CSN7/MDDR_TQ, J21 GPIO0_A[5]/FLASH_DQS, J22 GPIO0_D[5]/FLASH_CSN4, J23 GPIO4_B[2]/FLASH_DATA[10], J24 GPIO4_B[3]/FLASH_DATA[11], K19 FLASH_WP, K20 FLASH_WRN, K21 GPIO4_B[6]/FLASH_DATA[14], K22 GPIO0_D[3]/FLASH_CSN2, K23 GPIO0_D[4]/FLASH_CSN3, K24 GPIO0_D[2]/FLASH_CSN1, L19 FLASH_DATA[6], L20 GPIO4_B[0]/FLASH_DATA[8], L21 FLASH_DATA[7], L22 FLASH_DATA[2], L23 FLASH_DATA[3], L24 GPIO0_D[7]/FLASH_CSN6, M19 GPIO4_B[7]/FLASH_DATA[15], M20 GPIO4_B[5]/FLASH_DATA[13], M21 FLASH_CLE, M22 GPIO4_B[1]/FLASH_DATA[9], M23 FLASH_DATA[5], M24 FLASH_CSN0, N19 FLASH_DATA[1], N20 FLASH_RDY, N21 FLASH_RDN, N22 GPIO4_B[4]/FLASH_DATA[12], N23 FLASH_DATA[0], N24 FLASH_DATA[4], P19 FLASH_ALE
part F pins: A6 GPIO5_D[6]/SDMMC1_PWR_EN, A7 GPIO5_D[5]/SDMMC0_PWR_EN, B10 GPIO2_A[2]/SDMMC0_DETECT_N, B24 GPIO1_D[4]/SDMMC0_DATA2, C22 GPIO2_A[0]/SDMMC0_DATA6, C23 GPIO1_D[6]/SDMMC0_DATA4, D20 GPIO1_D[2]/SDMMC0_DATA0, D22 GPIO1_D[0]/SDMMC0_CLKOUT, D24 GPIO1_C[2]/SDMMC1_CMD, E20 GPIO1_D[7]/SDMMC0_DATA5, E23 GPIO2_A[1]/SDMMC0_DATA7, G19 GPIO1_D[5]/SDMMC0_DATA3, G20 GPIO1_D[1]/SDMMC0_CMD, G22 GPIO1_D[3]/SDMMC0_DATA1, G24 GPIO1_C[7]/SDMMC1_CLKOUT, H18 GPIO1_C[5]/SDMMC1_DATA2, H19 GPIO1_C[6]/SDMMC1_DATA3, H22 GPIO1_C[3]/SDMMC1_DATA0, H23 GPIO1_C[4]/SDMMC1_DATA1
part G pins: A18 GPIO4_C[5]/RMII_CRS_DVALID/MII_RXD_VALID, A20 GPIO4_C[0]/RMII_CLKOUT/RMII_CLKIN, A22 GPIO4_C[1]/RMII_TX_EN/MII_TX_EN, B18 GPIO5_A[3]/MII_TX_CLKIN, B23 GPIO4_C[6]/RMII_RXD1/MII_RXD1, C18 GPIO4_C[4]/RMII_RX_ERR/MII_RX_ERR, C19 GPIO4_C[2]/RMII_TXD1/MII_TXD1, D11 GPIO0_A[7]/MII_MDCLK, D18 GPIO0_A[6]/MII_MD, D21 GPIO4_C[3]/RMII_TXD0/MII_TXD0, E19 GPIO4_C[7]/RMII_RXD0/MII_RXD0, K5 TRST_N, L5 TCK, L6 TDI, M6 TMS, M7 TDO
part H pins: A17 GPIO5_B[3]/HSADC_DATA6, A19 GPIO5_A[7]/HSADC_DATA2, B17 GPIO5_B[2]/HSADC_DATA5, B19 GPIO5_B[5]/HSADC_DATA8/TS_VALID, B20 GPIO5_A[5]/HSADC_DATA0, C13 GPIO5_B[6]/HSADC_DATA9/TS_FAIL, C16 GPIO5_A[4]/TS_SYNC, C17 GPIO5_B[4]/HSADC_DATA7, C20 GPIO5_B[1]/HSADC_DATA4, E21 GPIO5_B[0]/HSADC_DATA3, F18 GPIO5_A[6]/HSADC_DATA1, F19 GPIO5_B[7]/HSADC_CLKOUT/GPS_CLK
part I pins: A3 GPIO1_C[0]/UART0_CTS_N/SDMMC1_DETECT_N, A4 GPIO3_A[5]/I2S1_LRCK_TX, A5 GPIO3_A[4]/I2S1_SDO, A8 GPIO2_B[2]/UART3_SIN, A10 GPIO1_A[4]/EMMC_WRITE_PRT/SPI0_CSN1, A12 GPIO1_A[6]/I2C1_SDA, A13 GPIO2_C[5]/SPI1_CSN0, A21 GPIO2_D[2]/I2S0_LRCK_RX/MII_TX_ERR, A23 GPIO2_D[5]/I2S0_SDO1/MII_RXD3, A24 GPIO2_D[6]/I2S0_SDO2/MII_TXD2, B4 GPIO2_A[7]/UART2_RTS_N, B5 GPIO3_A[3]/I2S1_SDI, B6 GPIO3_A[1]/I2S1_SCLK, B8 GPIO5_D[3]/I2C2_SDA, B12 GPIO1_A[7]/I2C1_SCL, B16 GPIO2_C[6]/SPI1_TXD, B21 GPIO4_D[7]/I2S0_LRCK_TX1, B22 GPIO2_D[3]/I2S0_SDI/MII_COL, C4 GPIO1_C[1]/UART0_RTS_N/SDMMC1_WRITE_PRT, C5 GPIO2_A[6]/UART2_CTS_N, C6 GPIO3_A[2]/I2S1_LRCK_RX, C7 GPIO2_A[4]/UART1_SIN, C9 GPIO2_B[6]/I2C0_SDA, C14 GPIO2_C[7]/SPI1_RXD, C15 GPIO4_A[7]/SPDIF_TX, C21 GPIO2_D[4]/I2S0_SDO0/MII_RXD2, C24 GPIO2_D[7]/I2S0_SDO3/MII_TXD3, D5 GPIO1_B[7]/UART0_SOUT, D6 GPIO2_B[4]/UART3_CTS_N/I2C3_SDA, D7 GPIO3_A[0]/I2S1_CLK, D8 GPIO1_B[6]/UART0_SIN, D9 GPIO5_D[4]/I2C2_SCL, D10 GPIO2_B[7]/I2C0_SCL, D14 GPIO2_C[0]/SPI0_CLK, D15 GPIO2_C[3]/SPI0_RXD, E6 GPIO2_B[0]/UART2_SIN, E7 GPIO2_B[5]/UART3_RTS_N/I2C3_SCL, E8 GPIO2_B[1]/UART2_SOUT, E9 GPIO2_A[5]/UART1_SOUT, E14 GPIO2_C[1]/SPI0_CSN0, E15 GPIO2_C[2]/SPI0_TXD, E24 GPIO2_D[0]/I2S0_CLK/MII_RX_CLKIN, F8 GPIO2_B[3]/UART3_SOUT, F15 GPIO1_A[3]/EMMC_DETECT_N/SPI1_CSN1, F16 GPIO2_C[4]/SPI1_CLK, F20 GPIO4_D[6]/I2S0_LRCK_TX0, H20 GPIO2_D[1]/I2S0_SCLK/MII_CRS
part J pins: A1 GPIO6_A[0], A2 GPIO6_B[7], A11 GPIO6_C[2], AA23 SARADC_AIN[0], AA24 SARADC_AIN[3], B1 GPIO6_B[6], B2 GPIO6_B[5], B3 GPIO6_A[1], B7 GPIO5_D[2]/PWM1/UART1_SIR_IN, B9 GPIO2_A[3]/SDMMC0_WRITE_PRT/PWM2/UART1_SIR_OUT, C1 GPIO6_A[5], C2 GPIO6_B[4], C3 GPIO6_A[2], C8 GPIO1_B[5]/PWM0, C10 GPIO4_D[4], C11 GPIO6_C[6], C12 GPIO6_C[0], D1 GPIO6_A[6], D2 GPIO6_A[7], D3 GPIO6_B[3], D4 GPIO6_A[3], D12 GPIO4_D[0], D13 GPIO6_C[3], E1 GPIO6_B[0], E2 GPIO5_A[0], E3 GPIO6_B[2], E4 GPIO5_A[2], E5 GPIO6_A[4], E10 GPIO6_C[5], E11 GPIO4_D[1], E12 GPIO6_C[1], E13 GPIO6_C[7], F1 GPIO6_B[1], F2 GPIO0_A[1], F3 GPIO5_A[1], F4 GPIO0_A[0], F9 GPIO4_D[3], F10 GPIO4_D[2], F11 GPIO4_D[5], F12 GPIO5_D[7], F13 GPIO6_C[4], G3 GPIO0_A[2], G4 GPIO0_A[4], H3 GPIO0_A[3], H4 GPIO4_A[3], J1 GPIO4_A[0], J2 GPIO4_A[1], J3 GPIO4_A[2], J4 GPIO4_A[4], N6 BTMODE, P7 EWAKEUP_STOP, P20 VDDCORE_EFUSE, R20 EFUSE_VQPS, T7 EWAKEUP_POWER, T19 VDDIO_EFUSE, V7 TEST, V8 GPIO6_D[2], V9 GPIO6_D[0], W7 GPIO6_D[3], W8 GPIO6_D[1], Y23 SARADC_AIN[1], Y24 SARADC_AIN[2]
part K pins: AB24 VDDA_SARADC, F5 AVDD_DPLL, F6 AHVDD_APLL, F7 AHVSS_APLL, G5 DVDD_APLL, G6 AVSS_DPLL, G7 DVSS_APLL, G8 VDDIO_AP1, G9 VDDIO_AP0, G10 VDDCORE, G11 VDDIO6, G12 VDDCORE, G13 VDDIO5, G14 VDDCORE, G15 VDDIO4, G16 VDDCORE, G18 VDDIO3, H5 DVDD_DPLL, H6 DVSS_DPLL, H7 DVSS_CGPLL, J5 AVDD_CGPLL, J6 DVDD_CGPLL, J7 AVSS_CGPLL, J18 VDDCORE, K7 VDDIO0, K10 GND, K11 GND, K12 GND, K13 GND, K14 GND, K15 GND, K18 VDDIO2, L7 VDDCORE, L10 GND, L11 GND, L12 GND, L13 GND, L14 GND, L15 GND, L18 VDDCORE, M5 VSSIO_DDR0, M10 GND, M11 GND, M12 GND, M13 GND, M14 GND, M15 GND, M18 VDDIO_FLASH1, N5 VDDIO_DDR0, N7 VDDCORE, N10 GND, N11 GND, N12 GND, N13 GND, N14 GND, N15 GND, N18 VDDCORE, P5 VSSIO_DDR1, P10 GND, P11 GND, P12 GND, P13 GND, P14 GND, P15 GND, P18 VDDIO_FLASH0, P21 VDDIO_RTC, R5 VDDIO_DDR1, R7 VDDCORE, R10 GND, R11 GND, R12 GND, R13 GND, R14 GND, R15 GND, R18 VDDCORE, R21 VSSIO_UHOST11, R22 VDDIO_UHOST11, T5 VSSIO_DDR2, T18 VDDIO1, T21 HOST20_VSSA, T22 HOST_VDD25, U5 VDDIO_DDR2, U7 VDDCORE, U18 VDDCORE_RTC, U19 HOST20_DVDD, U20 HOST20_VSSAC, U21 HOST20_DVSS, U23 HOST20_VDD33, V5 VSSIO_DDR3, V10 VDDCORE, V11 VDDIO_LCD0, V12 VDDCORE, V13 VDDIO_LCD1, V14 VDDCORE, V15 VDDIO_VIP, V16 VDDCORE, V17 VDDIO_SMC0, V18 VDDIO_SMC1, V19 OTG_DVDD, V21 OTG_VSSA, V22 OTG_VDD25, W5 VDDIO_DDR3, W20 OTG_VSSAC, W21 OTG_DVSS, W23 OTG_VDD33, Y5 VSSIO_DDR4, Y6 VDDIO_DDR4, Y7 VSSIO_DDR5, Y8 VDDIO_DDR5, Y9 VSSIO_DDR6, Y10 VDDIO_DDR6
part L pins: AA1 WE_B, AA2 CAS_B, AA3 ODT1, AA4 NC3, AA5 DLL_TEST_PIN[0], AA6 DQ12, AA7 DQ13, AA8 NC4, AA9 DQ28, AA10 DQ27, AB1 A10, AB2 RAS_B, AB3 NC2, AB4 A14, AB5 DQ9, AB6 DQ10, AB7 DM3, AB8 NC5, AB9 DQ26, AB10 DQ30, AC1 A8, AC2 A13, AC3 A7, AC4 DQ8, AC5 DM1, AC6 DQS1#, AC7 DQ14, AC8 DQ24, AC9 DQS3#, AC10 DQ29, AD1 A11, AD2 A15, AD3 A9, AD4 A12, AD5 DQ11, AD6 DQS1, AD7 DQ15, AD8 DQ25, AD9 DQS3, AD10 DQ31, K1 DQ3, K2 DQ2, K3 DQ1, K4 DQ0, L1 DQS0, L2 DQS0#, L3 DQ5, L4 DQ4, M1 DQ7, M2 DQ6, M3 DQ17, M4 DM0, N1 DQ19, N2 DQ18, N3 DM2, N4 DQ16, P1 DQS2, P2 DQS2#, P3 DQ21, P4 DQ20, P6 VREF0, R1 DQ23, R2 DQ22, R3 BA0, R4 ZQ_PIN, T1 A1, T2 A0, T3 BA1, T4 BA2, T6 ANALOG_TEST_PIN, U1 A2, U2 A3, U3 NC0, U4 NC1, U6 VREF1, V1 A6, V2 CS_B0, V3 A4, V4 A5, V6 RESET, W1 CS_B1, W2 ODT0, W3 CKE1, W4 RET_EN, W6 VREF2, W9 NC6, Y1 CK, Y2 CK#, Y3 CKE0, Y4 DLL_TEST_PIN[1]

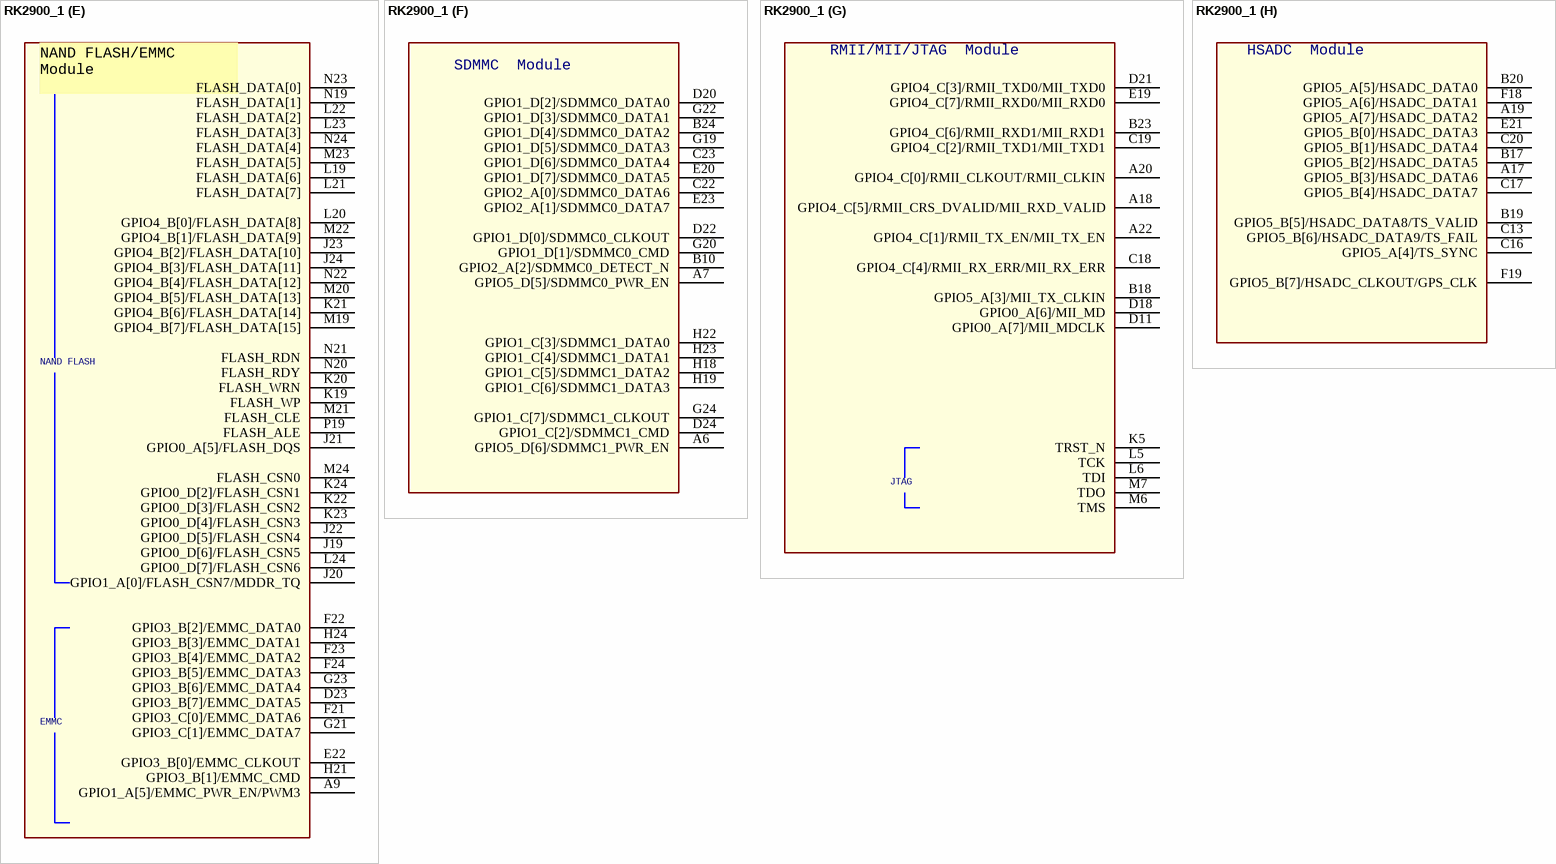
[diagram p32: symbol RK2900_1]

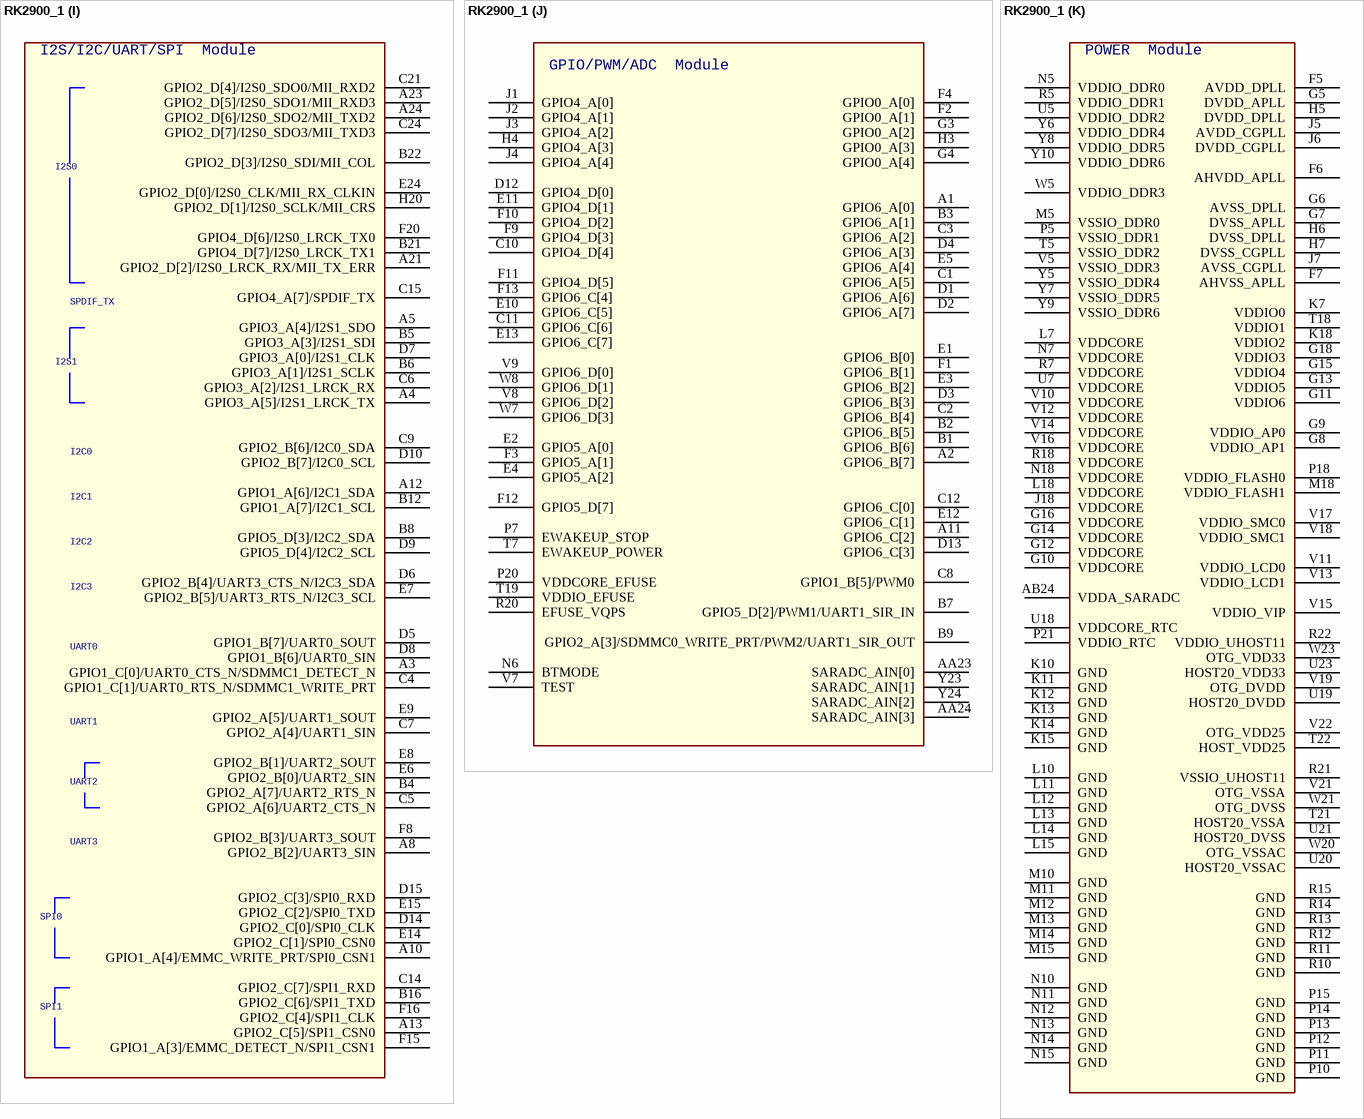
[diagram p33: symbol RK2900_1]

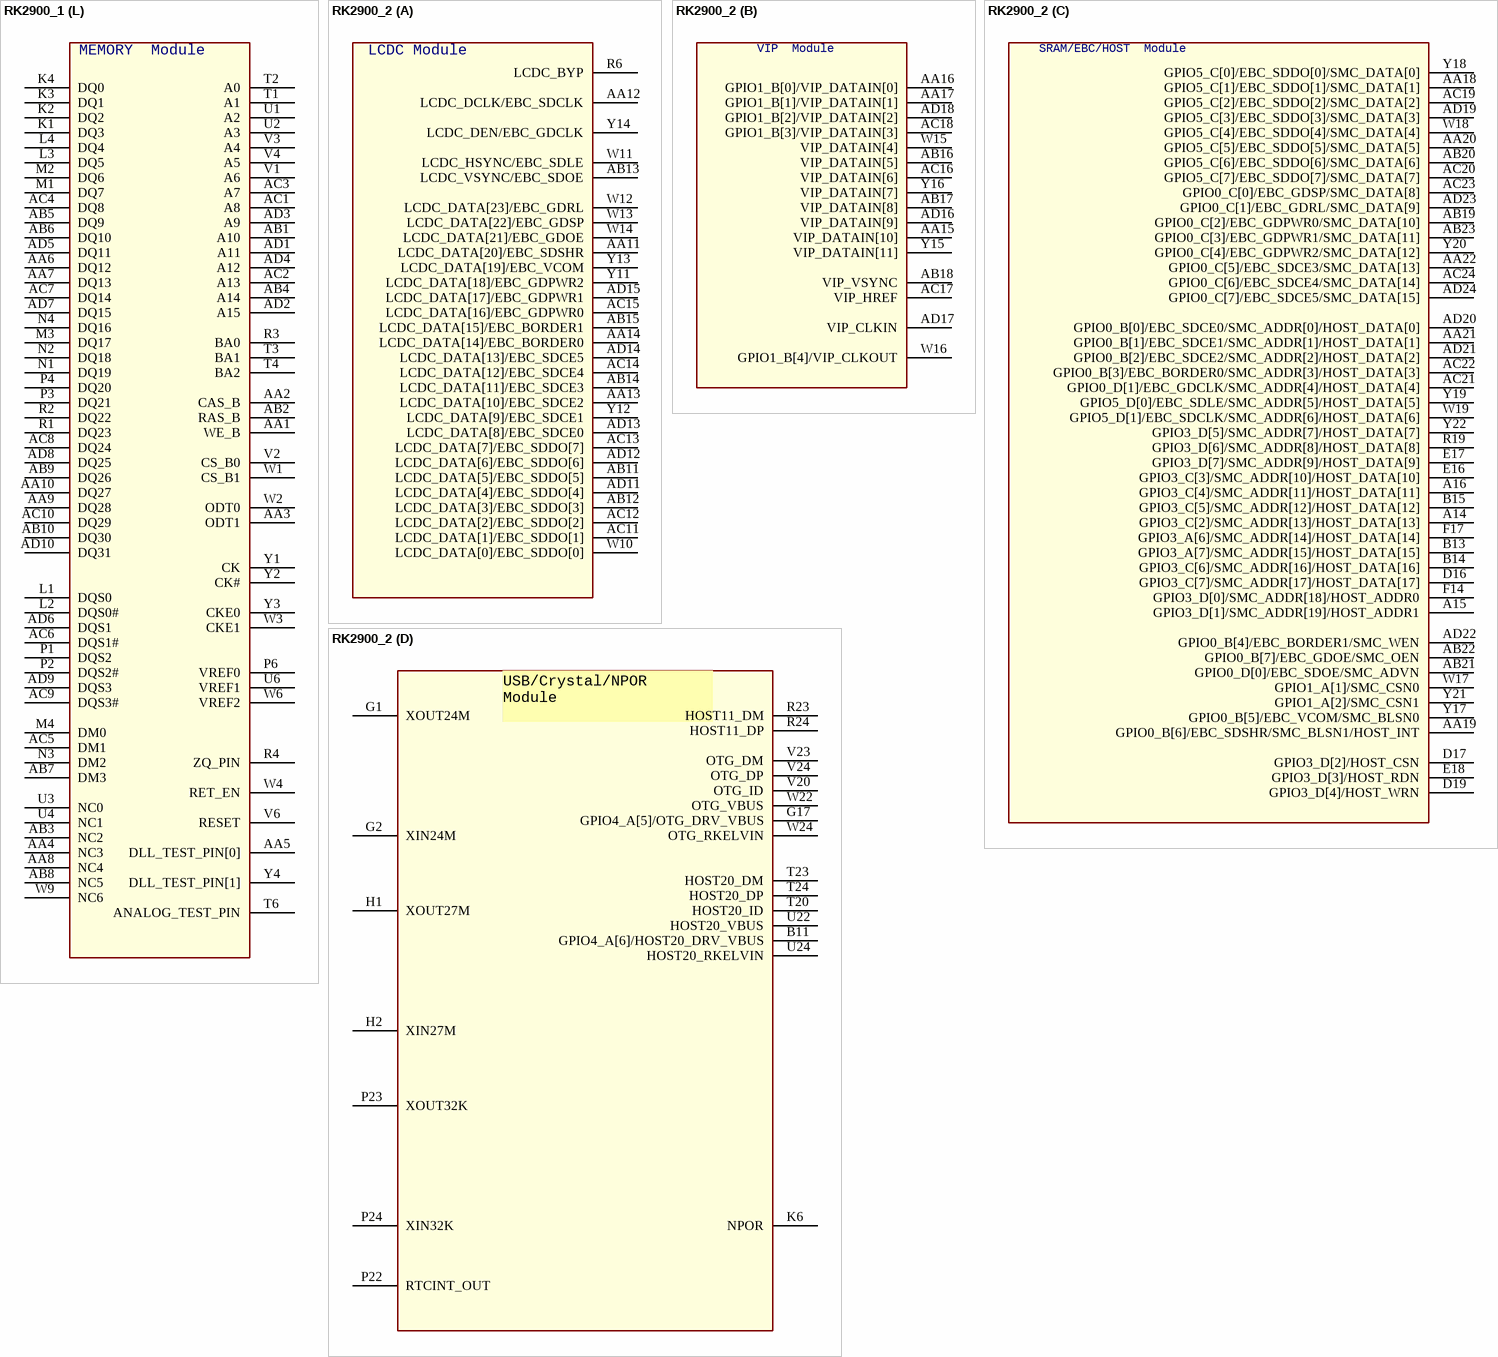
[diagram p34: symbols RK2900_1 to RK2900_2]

## RK2900_1
designator U?
Altium-Right: 120; Altium-Bottom: 610; Altium-Right1: 150; Altium-Bottom1: 700; Altium-Right2: 260; Altium-Bottom2: 469; Altium-Right3: 240; Altium-Bottom3: 690; Altium-Right4: 180; Altium-Bottom4: 200; Altium-Right5: 220; Altium-Bottom5: 340; Altium-Bottom6: 300; Altium-Right7: 190; Altium-Bottom7: 530; Altium-Right8: 250; Altium-Bottom8: 440; Altium-Right9: 280; Altium-Bottom9: 520; Altium-Right10: 140; Altium-Bottom10: 230; Altium-Right11: 160; Altium-Bottom11: 370
footprint BGA512
part A pins: AA11 LCDC_DATA[20]/EBC_SDSHR, AA12 LCDC_DCLK/EBC_SDCLK, AA13 LCDC_DATA[10]/EBC_SDCE2, AA14 LCDC_DATA[14]/EBC_BORDER0, AB11 LCDC_DATA[5]/EBC_SDDO[5], AB12 LCDC_DATA[3]/EBC_SDDO[3], AB13 LCDC_VSYNC/EBC_SDOE, AB14 LCDC_DATA[11]/EBC_SDCE3, AB15 LCDC_DATA[15]/EBC_BORDER1, AC11 LCDC_DATA[1]/EBC_SDDO[1], AC12 LCDC_DATA[2]/EBC_SDDO[2], AC13 LCDC_DATA[7]/EBC_SDDO[7], AC14 LCDC_DATA[12]/EBC_SDCE4, AC15 LCDC_DATA[16]/EBC_GDPWR0, AD11 LCDC_DATA[4]/EBC_SDDO[4], AD12 LCDC_DATA[6]/EBC_SDDO[6], AD13 LCDC_DATA[8]/EBC_SDCE0, AD14 LCDC_DATA[13]/EBC_SDCE5, AD15 LCDC_DATA[17]/EBC_GDPWR1, R6 LCDC_BYP, W10 LCDC_DATA[0]/EBC_SDDO[0], W11 LCDC_HSYNC/EBC_SDLE, W12 LCDC_DATA[23]/EBC_GDRL, W13 LCDC_DATA[22]/EBC_GDSP, W14 LCDC_DATA[21]/EBC_GDOE, Y11 LCDC_DATA[18]/EBC_GDPWR2, Y12 LCDC_DATA[9]/EBC_SDCE1, Y13 LCDC_DATA[19]/EBC_VCOM, Y14 LCDC_DEN/EBC_GDCLK
part B pins: AA15 VIP_DATAIN[10], AA16 GPIO1_B[0]/VIP_DATAIN[0], AA17 GPIO1_B[1]/VIP_DATAIN[1], AB16 VIP_DATAIN[5], AB17 VIP_DATAIN[8], AB18 VIP_VSYNC, AC16 VIP_DATAIN[6], AC17 VIP_HREF, AC18 GPIO1_B[3]/VIP_DATAIN[3], AD16 VIP_DATAIN[9], AD17 VIP_CLKIN, AD18 GPIO1_B[2]/VIP_DATAIN[2], W15 VIP_DATAIN[4], W16 GPIO1_B[4]/VIP_CLKOUT, Y15 VIP_DATAIN[11], Y16 VIP_DATAIN[7]
part C pins: A14 GPIO3_C[2]/SMC_ADDR[13]/HOST_DATA[13], A15 GPIO3_D[1]/SMC_ADDR[19]/HOST_ADDR1, A16 GPIO3_C[4]/SMC_ADDR[11]/HOST_DATA[11], AA18 GPIO5_C[1]/EBC_SDDO[1]/SMC_DATA[1], AA19 GPIO0_B[6]/EBC_SDSHR/SMC_BLSN1/HOST_INT, AA20 GPIO5_C[5]/EBC_SDDO[5]/SMC_DATA[5], AA21 GPIO0_B[1]/EBC_SDCE1/SMC_ADDR[1]/HOST_DATA[1], AA22 GPIO0_C[5]/EBC_SDCE3/SMC_DATA[13], AB19 GPIO0_C[2]/EBC_GDPWR0/SMC_DATA[10], AB20 GPIO5_C[6]/EBC_SDDO[6]/SMC_DATA[6], AB21 GPIO0_D[0]/EBC_SDOE/SMC_ADVN, AB22 GPIO0_B[7]/EBC_GDOE/SMC_OEN, AB23 GPIO0_C[3]/EBC_GDPWR1/SMC_DATA[11], AC19 GPIO5_C[2]/EBC_SDDO[2]/SMC_DATA[2], AC20 GPIO5_C[7]/EBC_SDDO[7]/SMC_DATA[7], AC21 GPIO0_D[1]/EBC_GDCLK/SMC_ADDR[4]/HOST_DATA[4], AC22 GPIO0_B[3]/EBC_BORDER0/SMC_ADDR[3]/HOST_DATA[3], AC23 GPIO0_C[0]/EBC_GDSP/SMC_DATA[8], AC24 GPIO0_C[6]/EBC_SDCE4/SMC_DATA[14], AD19 GPIO5_C[3]/EBC_SDDO[3]/SMC_DATA[3], AD20 GPIO0_B[0]/EBC_SDCE0/SMC_ADDR[0]/HOST_DATA[0], AD21 GPIO0_B[2]/EBC_SDCE2/SMC_ADDR[2]/HOST_DATA[2], AD22 GPIO0_B[4]/EBC_BORDER1/SMC_WEN, AD23 GPIO0_C[1]/EBC_GDRL/SMC_DATA[9], AD24 GPIO0_C[7]/EBC_SDCE5/SMC_DATA[15], B13 GPIO3_A[7]/SMC_ADDR[15]/HOST_DATA[15], B14 GPIO3_C[6]/SMC_ADDR[16]/HOST_DATA[16], B15 GPIO3_C[5]/SMC_ADDR[12]/HOST_DATA[12], D16 GPIO3_C[7]/SMC_ADDR[17]/HOST_DATA[17], D17 GPIO3_D[2]/HOST_CSN, D19 GPIO3_D[4]/HOST_WRN, E16 GPIO3_C[3]/SMC_ADDR[10]/HOST_DATA[10], E17 GPIO3_D[7]/SMC_ADDR[9]/HOST_DATA[9], E18 GPIO3_D[3]/HOST_RDN, F14 GPIO3_D[0]/SMC_ADDR[18]/HOST_ADDR0, F17 GPIO3_A[6]/SMC_ADDR[14]/HOST_DATA[14], R19 GPIO3_D[6]/SMC_ADDR[8]/HOST_DATA[8], W17 GPIO1_A[1]/SMC_CSN0, W18 GPIO5_C[4]/EBC_SDDO[4]/SMC_DATA[4], W19 GPIO5_D[1]/EBC_SDCLK/SMC_ADDR[6]/HOST_DATA[6], Y17 GPIO0_B[5]/EBC_VCOM/SMC_BLSN0, Y18 GPIO5_C[0]/EBC_SDDO[0]/SMC_DATA[0], Y19 GPIO5_D[0]/EBC_SDLE/SMC_ADDR[5]/HOST_DATA[5], Y20 GPIO0_C[4]/EBC_GDPWR2/SMC_DATA[12], Y21 GPIO1_A[2]/SMC_CSN1, Y22 GPIO3_D[5]/SMC_ADDR[7]/HOST_DATA[7]
part D pins: B11 GPIO4_A[6]/HOST20_DRV_VBUS, G1 XOUT24M, G2 XIN24M, G17 GPIO4_A[5]/OTG_DRV_VBUS, H1 XOUT27M, H2 XIN27M, K6 NPOR, P22 RTCINT_OUT, P23 XOUT32K, P24 XIN32K, R23 HOST11_DM, R24 HOST11_DP, T20 HOST20_ID, T23 HOST20_DM, T24 HOST20_DP, U22 HOST20_VBUS, U24 HOST20_RKELVIN, V20 OTG_ID, V23 OTG_DM, V24 OTG_DP, W22 OTG_VBUS, W24 OTG_RKELVIN
part E pins: A9 GPIO1_A[5]/EMMC_PWR_EN/PWM3, D23 GPIO3_B[7]/EMMC_DATA5, E22 GPIO3_B[0]/EMMC_CLKOUT, F21 GPIO3_C[0]/EMMC_DATA6, F22 GPIO3_B[2]/EMMC_DATA0, F23 GPIO3_B[4]/EMMC_DATA2, F24 GPIO3_B[5]/EMMC_DATA3, G21 GPIO3_C[1]/EMMC_DATA7, G23 GPIO3_B[6]/EMMC_DATA4, H21 GPIO3_B[1]/EMMC_CMD, H24 GPIO3_B[3]/EMMC_DATA1, J19 GPIO0_D[6]/FLASH_CSN5, J20 GPIO1_A[0]/FLASH_CSN7/MDDR_TQ, J21 GPIO0_A[5]/FLASH_DQS, J22 GPIO0_D[5]/FLASH_CSN4, J23 GPIO4_B[2]/FLASH_DATA[10], J24 GPIO4_B[3]/FLASH_DATA[11], K19 FLASH_WP, K20 FLASH_WRN, K21 GPIO4_B[6]/FLASH_DATA[14], K22 GPIO0_D[3]/FLASH_CSN2, K23 GPIO0_D[4]/FLASH_CSN3, K24 GPIO0_D[2]/FLASH_CSN1, L19 FLASH_DATA[6], L20 GPIO4_B[0]/FLASH_DATA[8], L21 FLASH_DATA[7], L22 FLASH_DATA[2], L23 FLASH_DATA[3], L24 GPIO0_D[7]/FLASH_CSN6, M19 GPIO4_B[7]/FLASH_DATA[15], M20 GPIO4_B[5]/FLASH_DATA[13], M21 FLASH_CLE, M22 GPIO4_B[1]/FLASH_DATA[9], M23 FLASH_DATA[5], M24 FLASH_CSN0, N19 FLASH_DATA[1], N20 FLASH_RDY, N21 FLASH_RDN, N22 GPIO4_B[4]/FLASH_DATA[12], N23 FLASH_DATA[0], N24 FLASH_DATA[4], P19 FLASH_ALE
part F pins: A6 GPIO5_D[6]/SDMMC1_PWR_EN, A7 GPIO5_D[5]/SDMMC0_PWR_EN, B10 GPIO2_A[2]/SDMMC0_DETECT_N, B24 GPIO1_D[4]/SDMMC0_DATA2, C22 GPIO2_A[0]/SDMMC0_DATA6, C23 GPIO1_D[6]/SDMMC0_DATA4, D20 GPIO1_D[2]/SDMMC0_DATA0, D22 GPIO1_D[0]/SDMMC0_CLKOUT, D24 GPIO1_C[2]/SDMMC1_CMD, E20 GPIO1_D[7]/SDMMC0_DATA5, E23 GPIO2_A[1]/SDMMC0_DATA7, G19 GPIO1_D[5]/SDMMC0_DATA3, G20 GPIO1_D[1]/SDMMC0_CMD, G22 GPIO1_D[3]/SDMMC0_DATA1, G24 GPIO1_C[7]/SDMMC1_CLKOUT, H18 GPIO1_C[5]/SDMMC1_DATA2, H19 GPIO1_C[6]/SDMMC1_DATA3, H22 GPIO1_C[3]/SDMMC1_DATA0, H23 GPIO1_C[4]/SDMMC1_DATA1
part G pins: A18 GPIO4_C[5]/RMII_CRS_DVALID/MII_RXD_VALID, A20 GPIO4_C[0]/RMII_CLKOUT/RMII_CLKIN, A22 GPIO4_C[1]/RMII_TX_EN/MII_TX_EN, B18 GPIO5_A[3]/MII_TX_CLKIN, B23 GPIO4_C[6]/RMII_RXD1/MII_RXD1, C18 GPIO4_C[4]/RMII_RX_ERR/MII_RX_ERR, C19 GPIO4_C[2]/RMII_TXD1/MII_TXD1, D11 GPIO0_A[7]/MII_MDCLK, D18 GPIO0_A[6]/MII_MD, D21 GPIO4_C[3]/RMII_TXD0/MII_TXD0, E19 GPIO4_C[7]/RMII_RXD0/MII_RXD0, K5 TRST_N, L5 TCK, L6 TDI, M6 TMS, M7 TDO
part H pins: A17 GPIO5_B[3]/HSADC_DATA6, A19 GPIO5_A[7]/HSADC_DATA2, B17 GPIO5_B[2]/HSADC_DATA5, B19 GPIO5_B[5]/HSADC_DATA8/TS_VALID, B20 GPIO5_A[5]/HSADC_DATA0, C13 GPIO5_B[6]/HSADC_DATA9/TS_FAIL, C16 GPIO5_A[4]/TS_SYNC, C17 GPIO5_B[4]/HSADC_DATA7, C20 GPIO5_B[1]/HSADC_DATA4, E21 GPIO5_B[0]/HSADC_DATA3, F18 GPIO5_A[6]/HSADC_DATA1, F19 GPIO5_B[7]/HSADC_CLKOUT/GPS_CLK
part I pins: A3 GPIO1_C[0]/UART0_CTS_N/SDMMC1_DETECT_N, A4 GPIO3_A[5]/I2S1_LRCK_TX, A5 GPIO3_A[4]/I2S1_SDO, A8 GPIO2_B[2]/UART3_SIN, A10 GPIO1_A[4]/EMMC_WRITE_PRT/SPI0_CSN1, A12 GPIO1_A[6]/I2C1_SDA, A13 GPIO2_C[5]/SPI1_CSN0, A21 GPIO2_D[2]/I2S0_LRCK_RX/MII_TX_ERR, A23 GPIO2_D[5]/I2S0_SDO1/MII_RXD3, A24 GPIO2_D[6]/I2S0_SDO2/MII_TXD2, B4 GPIO2_A[7]/UART2_RTS_N, B5 GPIO3_A[3]/I2S1_SDI, B6 GPIO3_A[1]/I2S1_SCLK, B8 GPIO5_D[3]/I2C2_SDA, B12 GPIO1_A[7]/I2C1_SCL, B16 GPIO2_C[6]/SPI1_TXD, B21 GPIO4_D[7]/I2S0_LRCK_TX1, B22 GPIO2_D[3]/I2S0_SDI/MII_COL, C4 GPIO1_C[1]/UART0_RTS_N/SDMMC1_WRITE_PRT, C5 GPIO2_A[6]/UART2_CTS_N, C6 GPIO3_A[2]/I2S1_LRCK_RX, C7 GPIO2_A[4]/UART1_SIN, C9 GPIO2_B[6]/I2C0_SDA, C14 GPIO2_C[7]/SPI1_RXD, C15 GPIO4_A[7]/SPDIF_TX, C21 GPIO2_D[4]/I2S0_SDO0/MII_RXD2, C24 GPIO2_D[7]/I2S0_SDO3/MII_TXD3, D5 GPIO1_B[7]/UART0_SOUT, D6 GPIO2_B[4]/UART3_CTS_N/I2C3_SDA, D7 GPIO3_A[0]/I2S1_CLK, D8 GPIO1_B[6]/UART0_SIN, D9 GPIO5_D[4]/I2C2_SCL, D10 GPIO2_B[7]/I2C0_SCL, D14 GPIO2_C[0]/SPI0_CLK, D15 GPIO2_C[3]/SPI0_RXD, E6 GPIO2_B[0]/UART2_SIN, E7 GPIO2_B[5]/UART3_RTS_N/I2C3_SCL, E8 GPIO2_B[1]/UART2_SOUT, E9 GPIO2_A[5]/UART1_SOUT, E14 GPIO2_C[1]/SPI0_CSN0, E15 GPIO2_C[2]/SPI0_TXD, E24 GPIO2_D[0]/I2S0_CLK/MII_RX_CLKIN, F8 GPIO2_B[3]/UART3_SOUT, F15 GPIO1_A[3]/EMMC_DETECT_N/SPI1_CSN1, F16 GPIO2_C[4]/SPI1_CLK, F20 GPIO4_D[6]/I2S0_LRCK_TX0, H20 GPIO2_D[1]/I2S0_SCLK/MII_CRS
part J pins: A1 GPIO6_A[0], A2 GPIO6_B[7], A11 GPIO6_C[2], AA23 SARADC_AIN[0], AA24 SARADC_AIN[3], B1 GPIO6_B[6], B2 GPIO6_B[5], B3 GPIO6_A[1], B7 GPIO5_D[2]/PWM1/UART1_SIR_IN, B9 GPIO2_A[3]/SDMMC0_WRITE_PRT/PWM2/UART1_SIR_OUT, C1 GPIO6_A[5], C2 GPIO6_B[4], C3 GPIO6_A[2], C8 GPIO1_B[5]/PWM0, C10 GPIO4_D[4], C11 GPIO6_C[6], C12 GPIO6_C[0], D1 GPIO6_A[6], D2 GPIO6_A[7], D3 GPIO6_B[3], D4 GPIO6_A[3], D12 GPIO4_D[0], D13 GPIO6_C[3], E1 GPIO6_B[0], E2 GPIO5_A[0], E3 GPIO6_B[2], E4 GPIO5_A[2], E5 GPIO6_A[4], E10 GPIO6_C[5], E11 GPIO4_D[1], E12 GPIO6_C[1], E13 GPIO6_C[7], F1 GPIO6_B[1], F2 GPIO0_A[1], F3 GPIO5_A[1], F4 GPIO0_A[0], F9 GPIO4_D[3], F10 GPIO4_D[2], F11 GPIO4_D[5], F12 GPIO5_D[7], F13 GPIO6_C[4], G3 GPIO0_A[2], G4 GPIO0_A[4], H3 GPIO0_A[3], H4 GPIO4_A[3], J1 GPIO4_A[0], J2 GPIO4_A[1], J3 GPIO4_A[2], J4 GPIO4_A[4], N6 BTMODE, P7 EWAKEUP_STOP, P20 VDDCORE_EFUSE, R20 EFUSE_VQPS, T7 EWAKEUP_POWER, T19 VDDIO_EFUSE, V7 TEST, V8 GPIO6_D[2], V9 GPIO6_D[0], W7 GPIO6_D[3], W8 GPIO6_D[1], Y23 SARADC_AIN[1], Y24 SARADC_AIN[2]
part K pins: AB24 VDDA_SARADC, F5 AVDD_DPLL, F6 AHVDD_APLL, F7 AHVSS_APLL, G5 DVDD_APLL, G6 AVSS_DPLL, G7 DVSS_APLL, G8 VDDIO_AP1, G9 VDDIO_AP0, G10 VDDCORE, G11 VDDIO6, G12 VDDCORE, G13 VDDIO5, G14 VDDCORE, G15 VDDIO4, G16 VDDCORE, G18 VDDIO3, H5 DVDD_DPLL, H6 DVSS_DPLL, H7 DVSS_CGPLL, J5 AVDD_CGPLL, J6 DVDD_CGPLL, J7 AVSS_CGPLL, J18 VDDCORE, K7 VDDIO0, K10 GND, K11 GND, K12 GND, K13 GND, K14 GND, K15 GND, K18 VDDIO2, L7 VDDCORE, L10 GND, L11 GND, L12 GND, L13 GND, L14 GND, L15 GND, L18 VDDCORE, M5 VSSIO_DDR0, M10 GND, M11 GND, M12 GND, M13 GND, M14 GND, M15 GND, M18 VDDIO_FLASH1, N5 VDDIO_DDR0, N7 VDDCORE, N10 GND, N11 GND, N12 GND, N13 GND, N14 GND, N15 GND, N18 VDDCORE, P5 VSSIO_DDR1, P10 GND, P11 GND, P12 GND, P13 GND, P14 GND, P15 GND, P18 VDDIO_FLASH0, P21 VDDIO_RTC, R5 VDDIO_DDR1, R7 VDDCORE, R10 GND, R11 GND, R12 GND, R13 GND, R14 GND, R15 GND, R18 VDDCORE, R21 VSSIO_UHOST11, R22 VDDIO_UHOST11, T5 VSSIO_DDR2, T18 VDDIO1, T21 HOST20_VSSA, T22 HOST_VDD25, U5 VDDIO_DDR2, U7 VDDCORE, U18 VDDCORE_RTC, U19 HOST20_DVDD, U20 HOST20_VSSAC, U21 HOST20_DVSS, U23 HOST20_VDD33, V5 VSSIO_DDR3, V10 VDDCORE, V11 VDDIO_LCD0, V12 VDDCORE, V13 VDDIO_LCD1, V14 VDDCORE, V15 VDDIO_VIP, V16 VDDCORE, V17 VDDIO_SMC0, V18 VDDIO_SMC1, V19 OTG_DVDD, V21 OTG_VSSA, V22 OTG_VDD25, W5 VDDIO_DDR3, W20 OTG_VSSAC, W21 OTG_DVSS, W23 OTG_VDD33, Y5 VSSIO_DDR4, Y6 VDDIO_DDR4, Y7 VSSIO_DDR5, Y8 VDDIO_DDR5, Y9 VSSIO_DDR6, Y10 VDDIO_DDR6
part L pins: AA1 WE_B, AA2 CAS_B, AA3 ODT1, AA4 NC3, AA5 DLL_TEST_PIN[0], AA6 DQ12, AA7 DQ13, AA8 NC4, AA9 DQ28, AA10 DQ27, AB1 A10, AB2 RAS_B, AB3 NC2, AB4 A14, AB5 DQ9, AB6 DQ10, AB7 DM3, AB8 NC5, AB9 DQ26, AB10 DQ30, AC1 A8, AC2 A13, AC3 A7, AC4 DQ8, AC5 DM1, AC6 DQS1#, AC7 DQ14, AC8 DQ24, AC9 DQS3#, AC10 DQ29, AD1 A11, AD2 A15, AD3 A9, AD4 A12, AD5 DQ11, AD6 DQS1, AD7 DQ15, AD8 DQ25, AD9 DQS3, AD10 DQ31, K1 DQ3, K2 DQ2, K3 DQ1, K4 DQ0, L1 DQS0, L2 DQS0#, L3 DQ5, L4 DQ4, M1 DQ7, M2 DQ6, M3 DQ17, M4 DM0, N1 DQ19, N2 DQ18, N3 DM2, N4 DQ16, P1 DQS2, P2 DQS2#, P3 DQ21, P4 DQ20, P6 VREF0, R1 DQ23, R2 DQ22, R3 BA0, R4 ZQ_PIN, T1 A1, T2 A0, T3 BA1, T4 BA2, T6 ANALOG_TEST_PIN, U1 A2, U2 A3, U3 NC0, U4 NC1, U6 VREF1, V1 A6, V2 CS_B0, V3 A4, V4 A5, V6 RESET, W1 CS_B1, W2 ODT0, W3 CKE1, W4 RET_EN, W6 VREF2, W9 NC6, Y1 CK, Y2 CK#, Y3 CKE0, Y4 DLL_TEST_PIN[1]

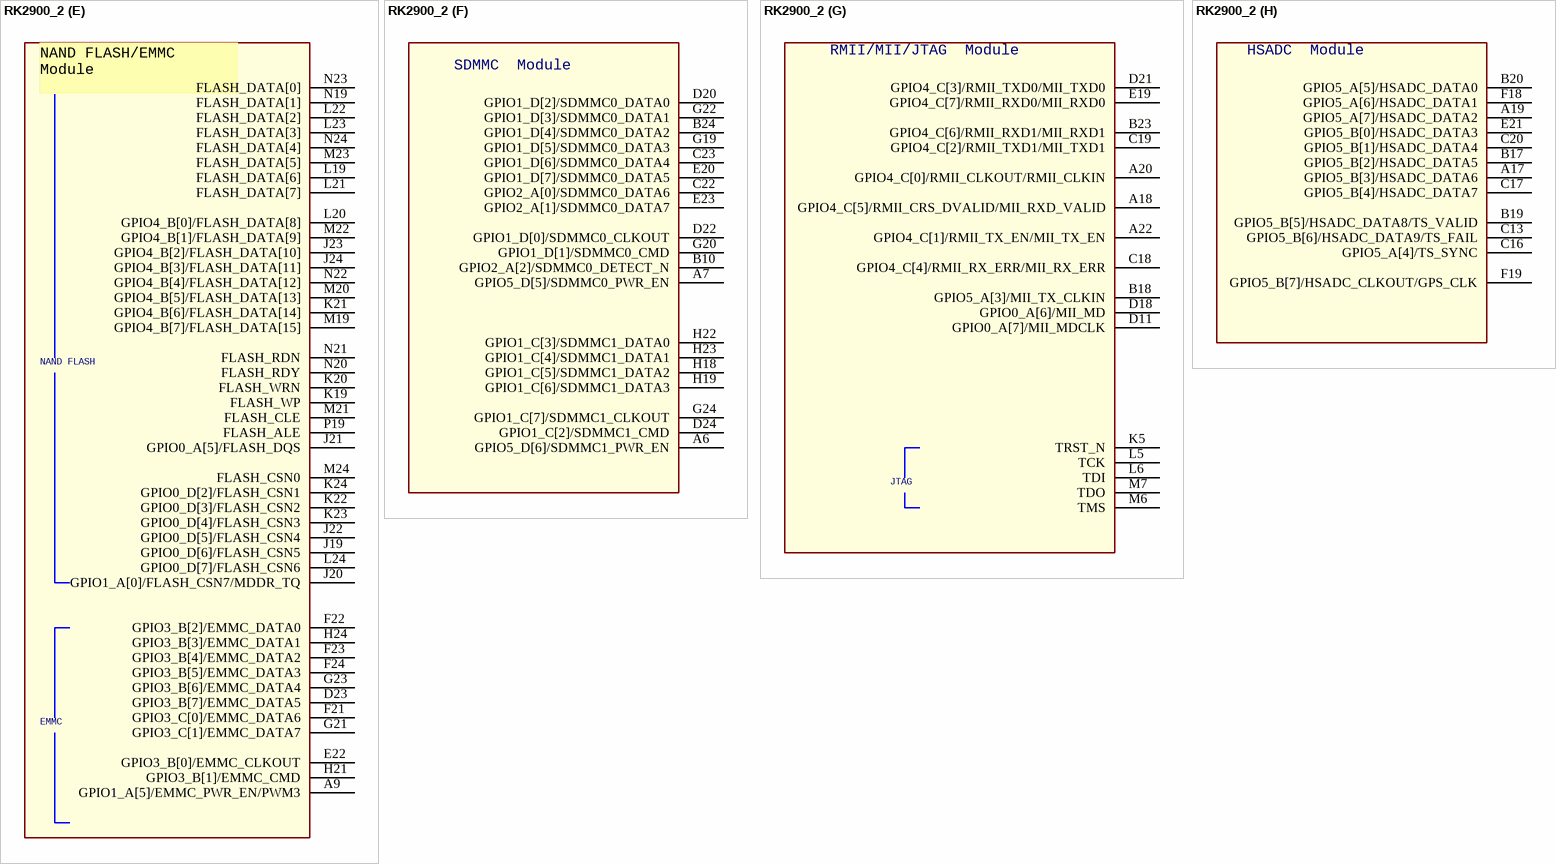
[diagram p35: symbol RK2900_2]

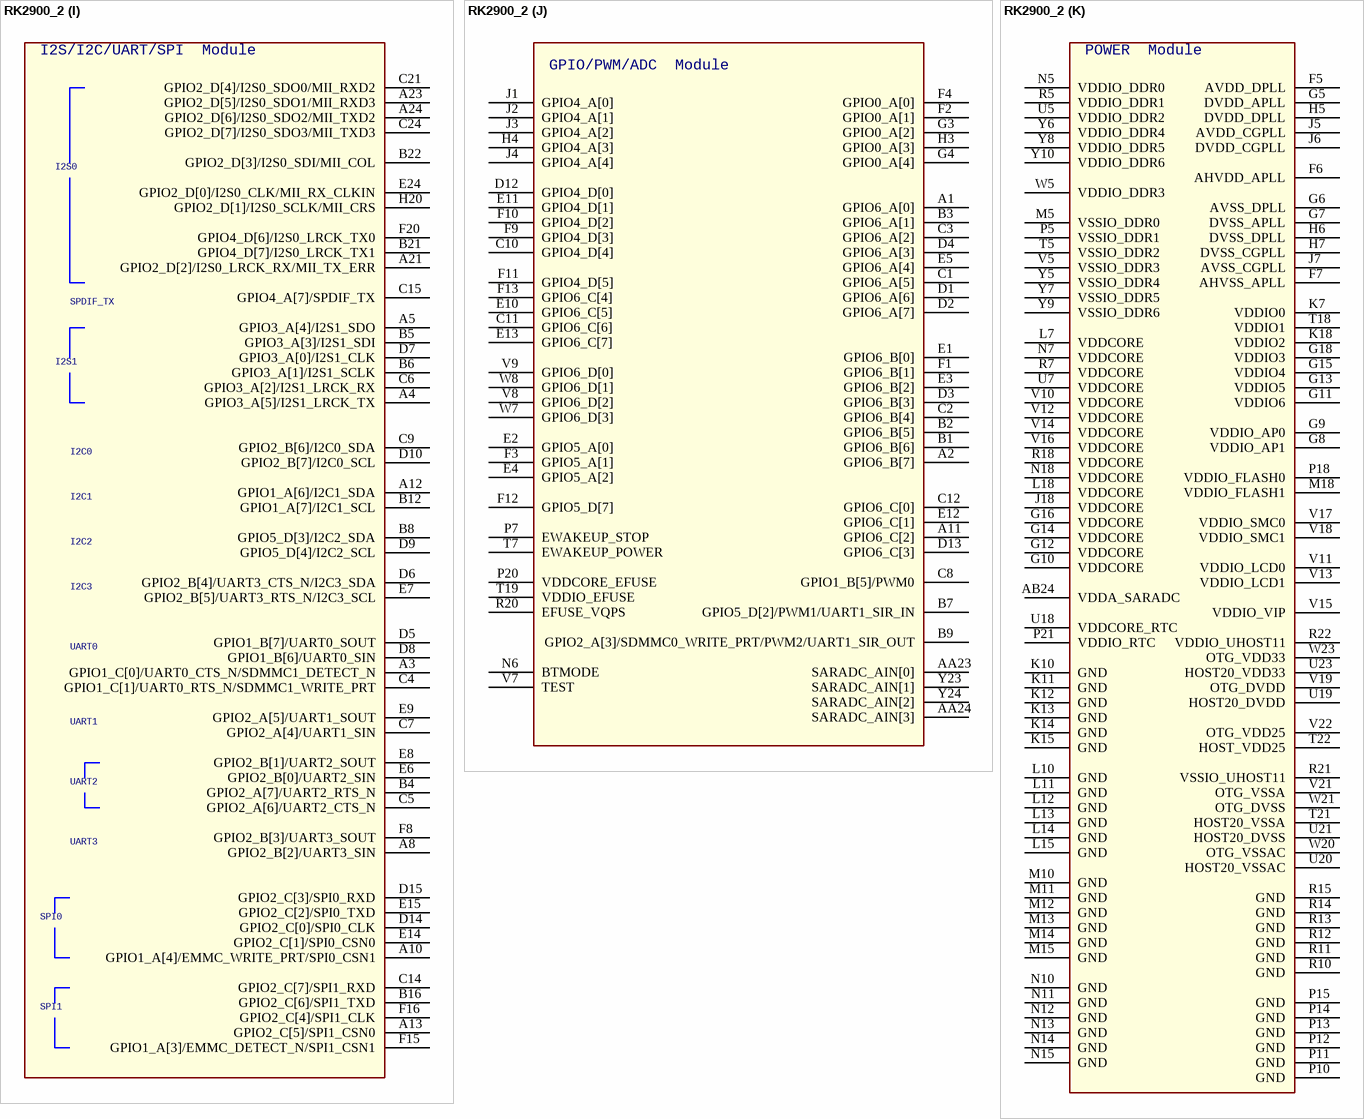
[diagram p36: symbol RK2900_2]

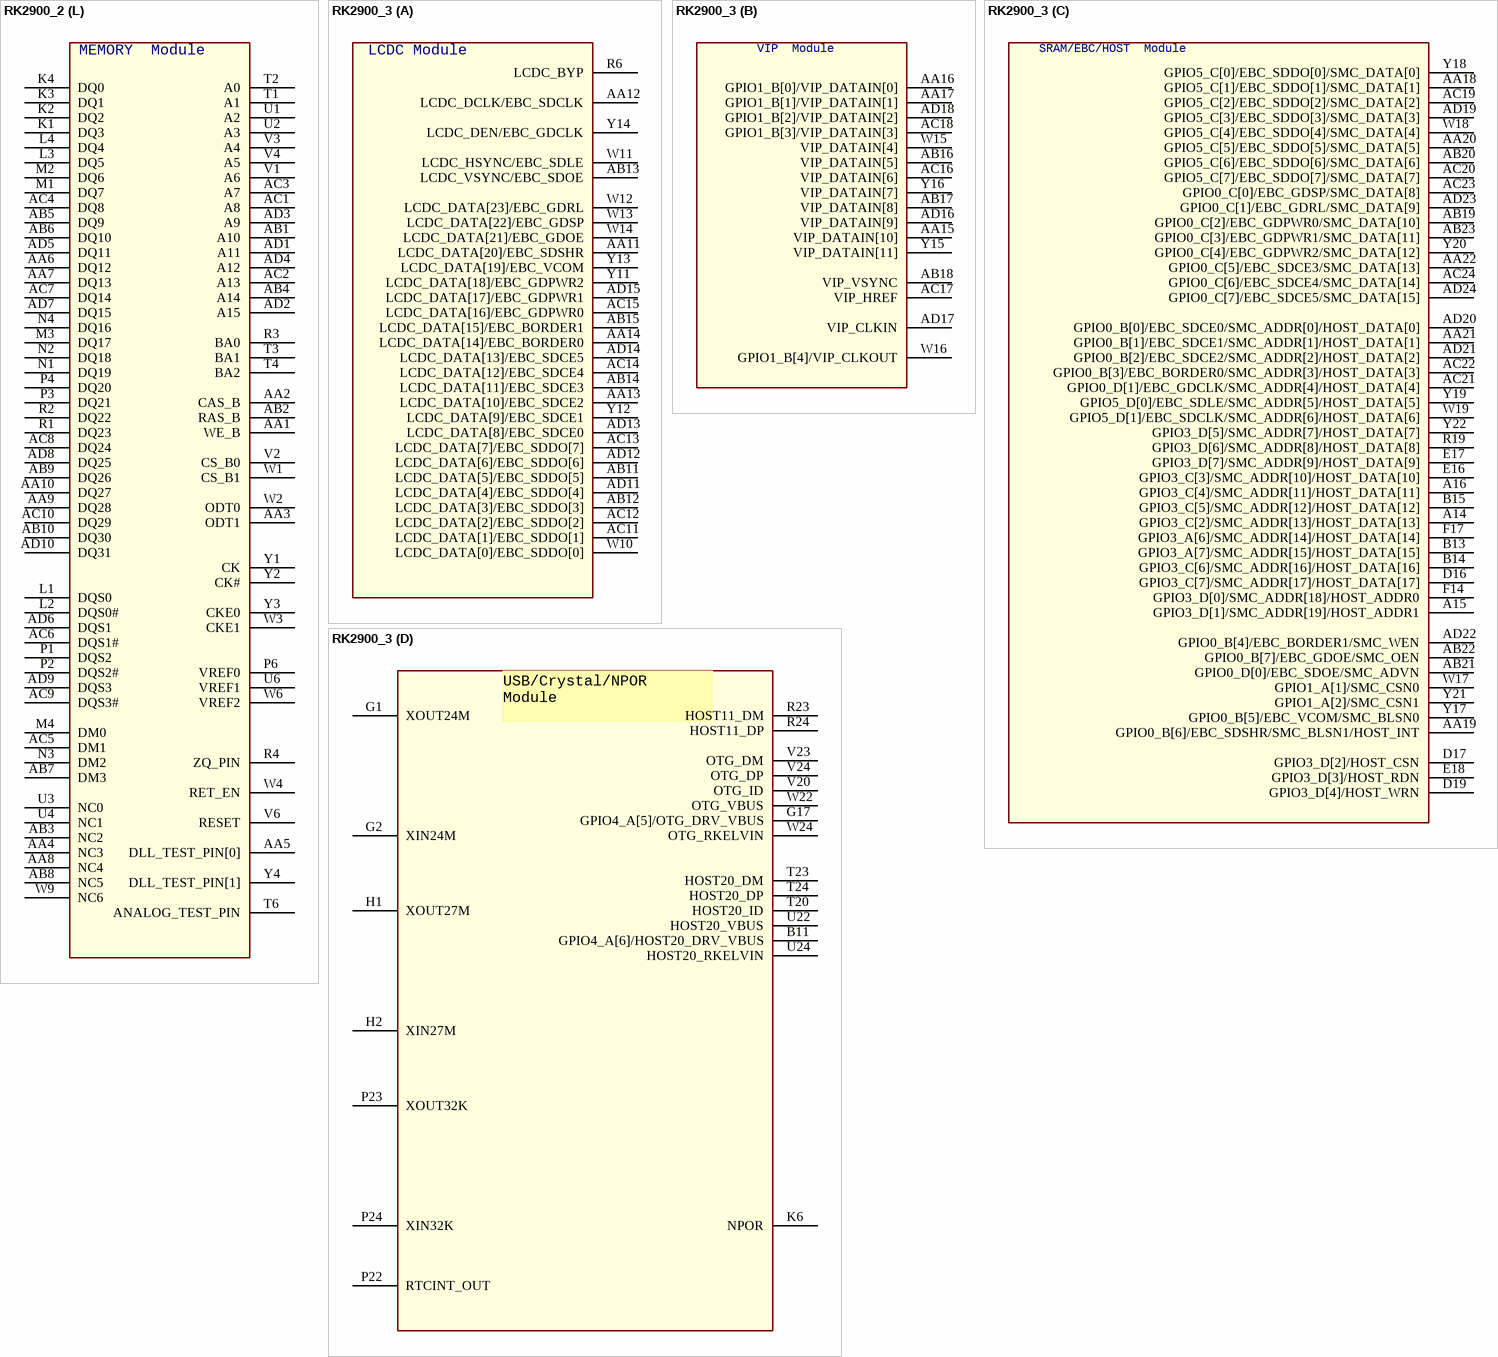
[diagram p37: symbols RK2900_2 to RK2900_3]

## RK2900_2
designator U?
Altium-Right: 120; Altium-Bottom: 610; Altium-Right1: 150; Altium-Bottom1: 700; Altium-Right2: 260; Altium-Bottom2: 469; Altium-Right3: 240; Altium-Bottom3: 690; Altium-Right4: 180; Altium-Bottom4: 200; Altium-Right5: 220; Altium-Bottom5: 340; Altium-Bottom6: 300; Altium-Right7: 190; Altium-Bottom7: 530; Altium-Right8: 250; Altium-Bottom8: 440; Altium-Right9: 280; Altium-Bottom9: 520; Altium-Right10: 140; Altium-Bottom10: 230; Altium-Right11: 160; Altium-Bottom11: 370
footprint BGA512
part A pins: AA11 LCDC_DATA[20]/EBC_SDSHR, AA12 LCDC_DCLK/EBC_SDCLK, AA13 LCDC_DATA[10]/EBC_SDCE2, AA14 LCDC_DATA[14]/EBC_BORDER0, AB11 LCDC_DATA[5]/EBC_SDDO[5], AB12 LCDC_DATA[3]/EBC_SDDO[3], AB13 LCDC_VSYNC/EBC_SDOE, AB14 LCDC_DATA[11]/EBC_SDCE3, AB15 LCDC_DATA[15]/EBC_BORDER1, AC11 LCDC_DATA[1]/EBC_SDDO[1], AC12 LCDC_DATA[2]/EBC_SDDO[2], AC13 LCDC_DATA[7]/EBC_SDDO[7], AC14 LCDC_DATA[12]/EBC_SDCE4, AC15 LCDC_DATA[16]/EBC_GDPWR0, AD11 LCDC_DATA[4]/EBC_SDDO[4], AD12 LCDC_DATA[6]/EBC_SDDO[6], AD13 LCDC_DATA[8]/EBC_SDCE0, AD14 LCDC_DATA[13]/EBC_SDCE5, AD15 LCDC_DATA[17]/EBC_GDPWR1, R6 LCDC_BYP, W10 LCDC_DATA[0]/EBC_SDDO[0], W11 LCDC_HSYNC/EBC_SDLE, W12 LCDC_DATA[23]/EBC_GDRL, W13 LCDC_DATA[22]/EBC_GDSP, W14 LCDC_DATA[21]/EBC_GDOE, Y11 LCDC_DATA[18]/EBC_GDPWR2, Y12 LCDC_DATA[9]/EBC_SDCE1, Y13 LCDC_DATA[19]/EBC_VCOM, Y14 LCDC_DEN/EBC_GDCLK
part B pins: AA15 VIP_DATAIN[10], AA16 GPIO1_B[0]/VIP_DATAIN[0], AA17 GPIO1_B[1]/VIP_DATAIN[1], AB16 VIP_DATAIN[5], AB17 VIP_DATAIN[8], AB18 VIP_VSYNC, AC16 VIP_DATAIN[6], AC17 VIP_HREF, AC18 GPIO1_B[3]/VIP_DATAIN[3], AD16 VIP_DATAIN[9], AD17 VIP_CLKIN, AD18 GPIO1_B[2]/VIP_DATAIN[2], W15 VIP_DATAIN[4], W16 GPIO1_B[4]/VIP_CLKOUT, Y15 VIP_DATAIN[11], Y16 VIP_DATAIN[7]
part C pins: A14 GPIO3_C[2]/SMC_ADDR[13]/HOST_DATA[13], A15 GPIO3_D[1]/SMC_ADDR[19]/HOST_ADDR1, A16 GPIO3_C[4]/SMC_ADDR[11]/HOST_DATA[11], AA18 GPIO5_C[1]/EBC_SDDO[1]/SMC_DATA[1], AA19 GPIO0_B[6]/EBC_SDSHR/SMC_BLSN1/HOST_INT, AA20 GPIO5_C[5]/EBC_SDDO[5]/SMC_DATA[5], AA21 GPIO0_B[1]/EBC_SDCE1/SMC_ADDR[1]/HOST_DATA[1], AA22 GPIO0_C[5]/EBC_SDCE3/SMC_DATA[13], AB19 GPIO0_C[2]/EBC_GDPWR0/SMC_DATA[10], AB20 GPIO5_C[6]/EBC_SDDO[6]/SMC_DATA[6], AB21 GPIO0_D[0]/EBC_SDOE/SMC_ADVN, AB22 GPIO0_B[7]/EBC_GDOE/SMC_OEN, AB23 GPIO0_C[3]/EBC_GDPWR1/SMC_DATA[11], AC19 GPIO5_C[2]/EBC_SDDO[2]/SMC_DATA[2], AC20 GPIO5_C[7]/EBC_SDDO[7]/SMC_DATA[7], AC21 GPIO0_D[1]/EBC_GDCLK/SMC_ADDR[4]/HOST_DATA[4], AC22 GPIO0_B[3]/EBC_BORDER0/SMC_ADDR[3]/HOST_DATA[3], AC23 GPIO0_C[0]/EBC_GDSP/SMC_DATA[8], AC24 GPIO0_C[6]/EBC_SDCE4/SMC_DATA[14], AD19 GPIO5_C[3]/EBC_SDDO[3]/SMC_DATA[3], AD20 GPIO0_B[0]/EBC_SDCE0/SMC_ADDR[0]/HOST_DATA[0], AD21 GPIO0_B[2]/EBC_SDCE2/SMC_ADDR[2]/HOST_DATA[2], AD22 GPIO0_B[4]/EBC_BORDER1/SMC_WEN, AD23 GPIO0_C[1]/EBC_GDRL/SMC_DATA[9], AD24 GPIO0_C[7]/EBC_SDCE5/SMC_DATA[15], B13 GPIO3_A[7]/SMC_ADDR[15]/HOST_DATA[15], B14 GPIO3_C[6]/SMC_ADDR[16]/HOST_DATA[16], B15 GPIO3_C[5]/SMC_ADDR[12]/HOST_DATA[12], D16 GPIO3_C[7]/SMC_ADDR[17]/HOST_DATA[17], D17 GPIO3_D[2]/HOST_CSN, D19 GPIO3_D[4]/HOST_WRN, E16 GPIO3_C[3]/SMC_ADDR[10]/HOST_DATA[10], E17 GPIO3_D[7]/SMC_ADDR[9]/HOST_DATA[9], E18 GPIO3_D[3]/HOST_RDN, F14 GPIO3_D[0]/SMC_ADDR[18]/HOST_ADDR0, F17 GPIO3_A[6]/SMC_ADDR[14]/HOST_DATA[14], R19 GPIO3_D[6]/SMC_ADDR[8]/HOST_DATA[8], W17 GPIO1_A[1]/SMC_CSN0, W18 GPIO5_C[4]/EBC_SDDO[4]/SMC_DATA[4], W19 GPIO5_D[1]/EBC_SDCLK/SMC_ADDR[6]/HOST_DATA[6], Y17 GPIO0_B[5]/EBC_VCOM/SMC_BLSN0, Y18 GPIO5_C[0]/EBC_SDDO[0]/SMC_DATA[0], Y19 GPIO5_D[0]/EBC_SDLE/SMC_ADDR[5]/HOST_DATA[5], Y20 GPIO0_C[4]/EBC_GDPWR2/SMC_DATA[12], Y21 GPIO1_A[2]/SMC_CSN1, Y22 GPIO3_D[5]/SMC_ADDR[7]/HOST_DATA[7]
part D pins: B11 GPIO4_A[6]/HOST20_DRV_VBUS, G1 XOUT24M, G2 XIN24M, G17 GPIO4_A[5]/OTG_DRV_VBUS, H1 XOUT27M, H2 XIN27M, K6 NPOR, P22 RTCINT_OUT, P23 XOUT32K, P24 XIN32K, R23 HOST11_DM, R24 HOST11_DP, T20 HOST20_ID, T23 HOST20_DM, T24 HOST20_DP, U22 HOST20_VBUS, U24 HOST20_RKELVIN, V20 OTG_ID, V23 OTG_DM, V24 OTG_DP, W22 OTG_VBUS, W24 OTG_RKELVIN
part E pins: A9 GPIO1_A[5]/EMMC_PWR_EN/PWM3, D23 GPIO3_B[7]/EMMC_DATA5, E22 GPIO3_B[0]/EMMC_CLKOUT, F21 GPIO3_C[0]/EMMC_DATA6, F22 GPIO3_B[2]/EMMC_DATA0, F23 GPIO3_B[4]/EMMC_DATA2, F24 GPIO3_B[5]/EMMC_DATA3, G21 GPIO3_C[1]/EMMC_DATA7, G23 GPIO3_B[6]/EMMC_DATA4, H21 GPIO3_B[1]/EMMC_CMD, H24 GPIO3_B[3]/EMMC_DATA1, J19 GPIO0_D[6]/FLASH_CSN5, J20 GPIO1_A[0]/FLASH_CSN7/MDDR_TQ, J21 GPIO0_A[5]/FLASH_DQS, J22 GPIO0_D[5]/FLASH_CSN4, J23 GPIO4_B[2]/FLASH_DATA[10], J24 GPIO4_B[3]/FLASH_DATA[11], K19 FLASH_WP, K20 FLASH_WRN, K21 GPIO4_B[6]/FLASH_DATA[14], K22 GPIO0_D[3]/FLASH_CSN2, K23 GPIO0_D[4]/FLASH_CSN3, K24 GPIO0_D[2]/FLASH_CSN1, L19 FLASH_DATA[6], L20 GPIO4_B[0]/FLASH_DATA[8], L21 FLASH_DATA[7], L22 FLASH_DATA[2], L23 FLASH_DATA[3], L24 GPIO0_D[7]/FLASH_CSN6, M19 GPIO4_B[7]/FLASH_DATA[15], M20 GPIO4_B[5]/FLASH_DATA[13], M21 FLASH_CLE, M22 GPIO4_B[1]/FLASH_DATA[9], M23 FLASH_DATA[5], M24 FLASH_CSN0, N19 FLASH_DATA[1], N20 FLASH_RDY, N21 FLASH_RDN, N22 GPIO4_B[4]/FLASH_DATA[12], N23 FLASH_DATA[0], N24 FLASH_DATA[4], P19 FLASH_ALE
part F pins: A6 GPIO5_D[6]/SDMMC1_PWR_EN, A7 GPIO5_D[5]/SDMMC0_PWR_EN, B10 GPIO2_A[2]/SDMMC0_DETECT_N, B24 GPIO1_D[4]/SDMMC0_DATA2, C22 GPIO2_A[0]/SDMMC0_DATA6, C23 GPIO1_D[6]/SDMMC0_DATA4, D20 GPIO1_D[2]/SDMMC0_DATA0, D22 GPIO1_D[0]/SDMMC0_CLKOUT, D24 GPIO1_C[2]/SDMMC1_CMD, E20 GPIO1_D[7]/SDMMC0_DATA5, E23 GPIO2_A[1]/SDMMC0_DATA7, G19 GPIO1_D[5]/SDMMC0_DATA3, G20 GPIO1_D[1]/SDMMC0_CMD, G22 GPIO1_D[3]/SDMMC0_DATA1, G24 GPIO1_C[7]/SDMMC1_CLKOUT, H18 GPIO1_C[5]/SDMMC1_DATA2, H19 GPIO1_C[6]/SDMMC1_DATA3, H22 GPIO1_C[3]/SDMMC1_DATA0, H23 GPIO1_C[4]/SDMMC1_DATA1
part G pins: A18 GPIO4_C[5]/RMII_CRS_DVALID/MII_RXD_VALID, A20 GPIO4_C[0]/RMII_CLKOUT/RMII_CLKIN, A22 GPIO4_C[1]/RMII_TX_EN/MII_TX_EN, B18 GPIO5_A[3]/MII_TX_CLKIN, B23 GPIO4_C[6]/RMII_RXD1/MII_RXD1, C18 GPIO4_C[4]/RMII_RX_ERR/MII_RX_ERR, C19 GPIO4_C[2]/RMII_TXD1/MII_TXD1, D11 GPIO0_A[7]/MII_MDCLK, D18 GPIO0_A[6]/MII_MD, D21 GPIO4_C[3]/RMII_TXD0/MII_TXD0, E19 GPIO4_C[7]/RMII_RXD0/MII_RXD0, K5 TRST_N, L5 TCK, L6 TDI, M6 TMS, M7 TDO
part H pins: A17 GPIO5_B[3]/HSADC_DATA6, A19 GPIO5_A[7]/HSADC_DATA2, B17 GPIO5_B[2]/HSADC_DATA5, B19 GPIO5_B[5]/HSADC_DATA8/TS_VALID, B20 GPIO5_A[5]/HSADC_DATA0, C13 GPIO5_B[6]/HSADC_DATA9/TS_FAIL, C16 GPIO5_A[4]/TS_SYNC, C17 GPIO5_B[4]/HSADC_DATA7, C20 GPIO5_B[1]/HSADC_DATA4, E21 GPIO5_B[0]/HSADC_DATA3, F18 GPIO5_A[6]/HSADC_DATA1, F19 GPIO5_B[7]/HSADC_CLKOUT/GPS_CLK
part I pins: A3 GPIO1_C[0]/UART0_CTS_N/SDMMC1_DETECT_N, A4 GPIO3_A[5]/I2S1_LRCK_TX, A5 GPIO3_A[4]/I2S1_SDO, A8 GPIO2_B[2]/UART3_SIN, A10 GPIO1_A[4]/EMMC_WRITE_PRT/SPI0_CSN1, A12 GPIO1_A[6]/I2C1_SDA, A13 GPIO2_C[5]/SPI1_CSN0, A21 GPIO2_D[2]/I2S0_LRCK_RX/MII_TX_ERR, A23 GPIO2_D[5]/I2S0_SDO1/MII_RXD3, A24 GPIO2_D[6]/I2S0_SDO2/MII_TXD2, B4 GPIO2_A[7]/UART2_RTS_N, B5 GPIO3_A[3]/I2S1_SDI, B6 GPIO3_A[1]/I2S1_SCLK, B8 GPIO5_D[3]/I2C2_SDA, B12 GPIO1_A[7]/I2C1_SCL, B16 GPIO2_C[6]/SPI1_TXD, B21 GPIO4_D[7]/I2S0_LRCK_TX1, B22 GPIO2_D[3]/I2S0_SDI/MII_COL, C4 GPIO1_C[1]/UART0_RTS_N/SDMMC1_WRITE_PRT, C5 GPIO2_A[6]/UART2_CTS_N, C6 GPIO3_A[2]/I2S1_LRCK_RX, C7 GPIO2_A[4]/UART1_SIN, C9 GPIO2_B[6]/I2C0_SDA, C14 GPIO2_C[7]/SPI1_RXD, C15 GPIO4_A[7]/SPDIF_TX, C21 GPIO2_D[4]/I2S0_SDO0/MII_RXD2, C24 GPIO2_D[7]/I2S0_SDO3/MII_TXD3, D5 GPIO1_B[7]/UART0_SOUT, D6 GPIO2_B[4]/UART3_CTS_N/I2C3_SDA, D7 GPIO3_A[0]/I2S1_CLK, D8 GPIO1_B[6]/UART0_SIN, D9 GPIO5_D[4]/I2C2_SCL, D10 GPIO2_B[7]/I2C0_SCL, D14 GPIO2_C[0]/SPI0_CLK, D15 GPIO2_C[3]/SPI0_RXD, E6 GPIO2_B[0]/UART2_SIN, E7 GPIO2_B[5]/UART3_RTS_N/I2C3_SCL, E8 GPIO2_B[1]/UART2_SOUT, E9 GPIO2_A[5]/UART1_SOUT, E14 GPIO2_C[1]/SPI0_CSN0, E15 GPIO2_C[2]/SPI0_TXD, E24 GPIO2_D[0]/I2S0_CLK/MII_RX_CLKIN, F8 GPIO2_B[3]/UART3_SOUT, F15 GPIO1_A[3]/EMMC_DETECT_N/SPI1_CSN1, F16 GPIO2_C[4]/SPI1_CLK, F20 GPIO4_D[6]/I2S0_LRCK_TX0, H20 GPIO2_D[1]/I2S0_SCLK/MII_CRS
part J pins: A1 GPIO6_A[0], A2 GPIO6_B[7], A11 GPIO6_C[2], AA23 SARADC_AIN[0], AA24 SARADC_AIN[3], B1 GPIO6_B[6], B2 GPIO6_B[5], B3 GPIO6_A[1], B7 GPIO5_D[2]/PWM1/UART1_SIR_IN, B9 GPIO2_A[3]/SDMMC0_WRITE_PRT/PWM2/UART1_SIR_OUT, C1 GPIO6_A[5], C2 GPIO6_B[4], C3 GPIO6_A[2], C8 GPIO1_B[5]/PWM0, C10 GPIO4_D[4], C11 GPIO6_C[6], C12 GPIO6_C[0], D1 GPIO6_A[6], D2 GPIO6_A[7], D3 GPIO6_B[3], D4 GPIO6_A[3], D12 GPIO4_D[0], D13 GPIO6_C[3], E1 GPIO6_B[0], E2 GPIO5_A[0], E3 GPIO6_B[2], E4 GPIO5_A[2], E5 GPIO6_A[4], E10 GPIO6_C[5], E11 GPIO4_D[1], E12 GPIO6_C[1], E13 GPIO6_C[7], F1 GPIO6_B[1], F2 GPIO0_A[1], F3 GPIO5_A[1], F4 GPIO0_A[0], F9 GPIO4_D[3], F10 GPIO4_D[2], F11 GPIO4_D[5], F12 GPIO5_D[7], F13 GPIO6_C[4], G3 GPIO0_A[2], G4 GPIO0_A[4], H3 GPIO0_A[3], H4 GPIO4_A[3], J1 GPIO4_A[0], J2 GPIO4_A[1], J3 GPIO4_A[2], J4 GPIO4_A[4], N6 BTMODE, P7 EWAKEUP_STOP, P20 VDDCORE_EFUSE, R20 EFUSE_VQPS, T7 EWAKEUP_POWER, T19 VDDIO_EFUSE, V7 TEST, V8 GPIO6_D[2], V9 GPIO6_D[0], W7 GPIO6_D[3], W8 GPIO6_D[1], Y23 SARADC_AIN[1], Y24 SARADC_AIN[2]
part K pins: AB24 VDDA_SARADC, F5 AVDD_DPLL, F6 AHVDD_APLL, F7 AHVSS_APLL, G5 DVDD_APLL, G6 AVSS_DPLL, G7 DVSS_APLL, G8 VDDIO_AP1, G9 VDDIO_AP0, G10 VDDCORE, G11 VDDIO6, G12 VDDCORE, G13 VDDIO5, G14 VDDCORE, G15 VDDIO4, G16 VDDCORE, G18 VDDIO3, H5 DVDD_DPLL, H6 DVSS_DPLL, H7 DVSS_CGPLL, J5 AVDD_CGPLL, J6 DVDD_CGPLL, J7 AVSS_CGPLL, J18 VDDCORE, K7 VDDIO0, K10 GND, K11 GND, K12 GND, K13 GND, K14 GND, K15 GND, K18 VDDIO2, L7 VDDCORE, L10 GND, L11 GND, L12 GND, L13 GND, L14 GND, L15 GND, L18 VDDCORE, M5 VSSIO_DDR0, M10 GND, M11 GND, M12 GND, M13 GND, M14 GND, M15 GND, M18 VDDIO_FLASH1, N5 VDDIO_DDR0, N7 VDDCORE, N10 GND, N11 GND, N12 GND, N13 GND, N14 GND, N15 GND, N18 VDDCORE, P5 VSSIO_DDR1, P10 GND, P11 GND, P12 GND, P13 GND, P14 GND, P15 GND, P18 VDDIO_FLASH0, P21 VDDIO_RTC, R5 VDDIO_DDR1, R7 VDDCORE, R10 GND, R11 GND, R12 GND, R13 GND, R14 GND, R15 GND, R18 VDDCORE, R21 VSSIO_UHOST11, R22 VDDIO_UHOST11, T5 VSSIO_DDR2, T18 VDDIO1, T21 HOST20_VSSA, T22 HOST_VDD25, U5 VDDIO_DDR2, U7 VDDCORE, U18 VDDCORE_RTC, U19 HOST20_DVDD, U20 HOST20_VSSAC, U21 HOST20_DVSS, U23 HOST20_VDD33, V5 VSSIO_DDR3, V10 VDDCORE, V11 VDDIO_LCD0, V12 VDDCORE, V13 VDDIO_LCD1, V14 VDDCORE, V15 VDDIO_VIP, V16 VDDCORE, V17 VDDIO_SMC0, V18 VDDIO_SMC1, V19 OTG_DVDD, V21 OTG_VSSA, V22 OTG_VDD25, W5 VDDIO_DDR3, W20 OTG_VSSAC, W21 OTG_DVSS, W23 OTG_VDD33, Y5 VSSIO_DDR4, Y6 VDDIO_DDR4, Y7 VSSIO_DDR5, Y8 VDDIO_DDR5, Y9 VSSIO_DDR6, Y10 VDDIO_DDR6
part L pins: AA1 WE_B, AA2 CAS_B, AA3 ODT1, AA4 NC3, AA5 DLL_TEST_PIN[0], AA6 DQ12, AA7 DQ13, AA8 NC4, AA9 DQ28, AA10 DQ27, AB1 A10, AB2 RAS_B, AB3 NC2, AB4 A14, AB5 DQ9, AB6 DQ10, AB7 DM3, AB8 NC5, AB9 DQ26, AB10 DQ30, AC1 A8, AC2 A13, AC3 A7, AC4 DQ8, AC5 DM1, AC6 DQS1#, AC7 DQ14, AC8 DQ24, AC9 DQS3#, AC10 DQ29, AD1 A11, AD2 A15, AD3 A9, AD4 A12, AD5 DQ11, AD6 DQS1, AD7 DQ15, AD8 DQ25, AD9 DQS3, AD10 DQ31, K1 DQ3, K2 DQ2, K3 DQ1, K4 DQ0, L1 DQS0, L2 DQS0#, L3 DQ5, L4 DQ4, M1 DQ7, M2 DQ6, M3 DQ17, M4 DM0, N1 DQ19, N2 DQ18, N3 DM2, N4 DQ16, P1 DQS2, P2 DQS2#, P3 DQ21, P4 DQ20, P6 VREF0, R1 DQ23, R2 DQ22, R3 BA0, R4 ZQ_PIN, T1 A1, T2 A0, T3 BA1, T4 BA2, T6 ANALOG_TEST_PIN, U1 A2, U2 A3, U3 NC0, U4 NC1, U6 VREF1, V1 A6, V2 CS_B0, V3 A4, V4 A5, V6 RESET, W1 CS_B1, W2 ODT0, W3 CKE1, W4 RET_EN, W6 VREF2, W9 NC6, Y1 CK, Y2 CK#, Y3 CKE0, Y4 DLL_TEST_PIN[1]

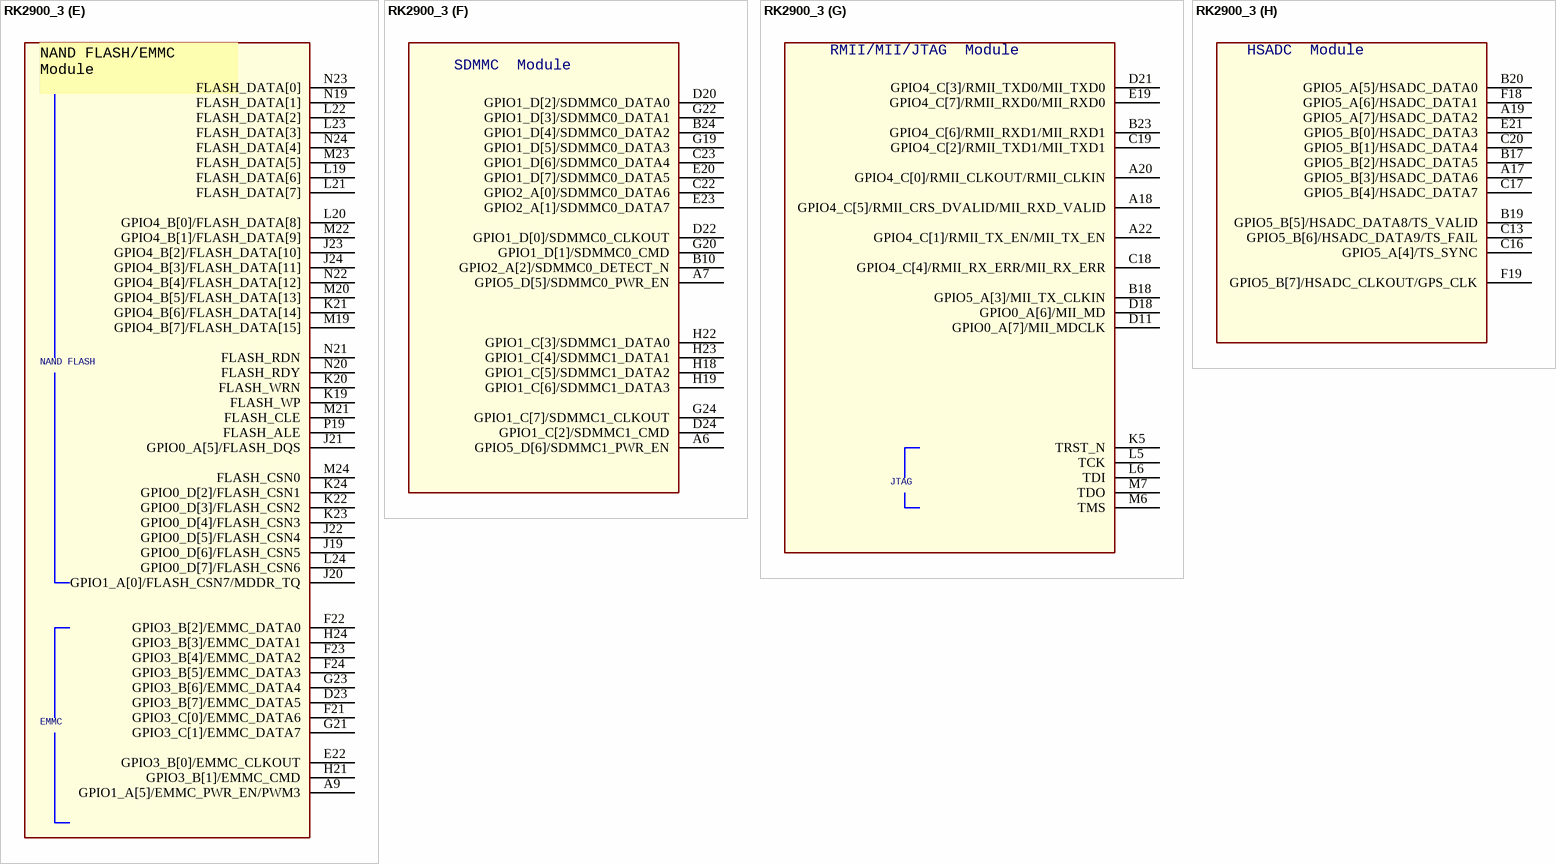
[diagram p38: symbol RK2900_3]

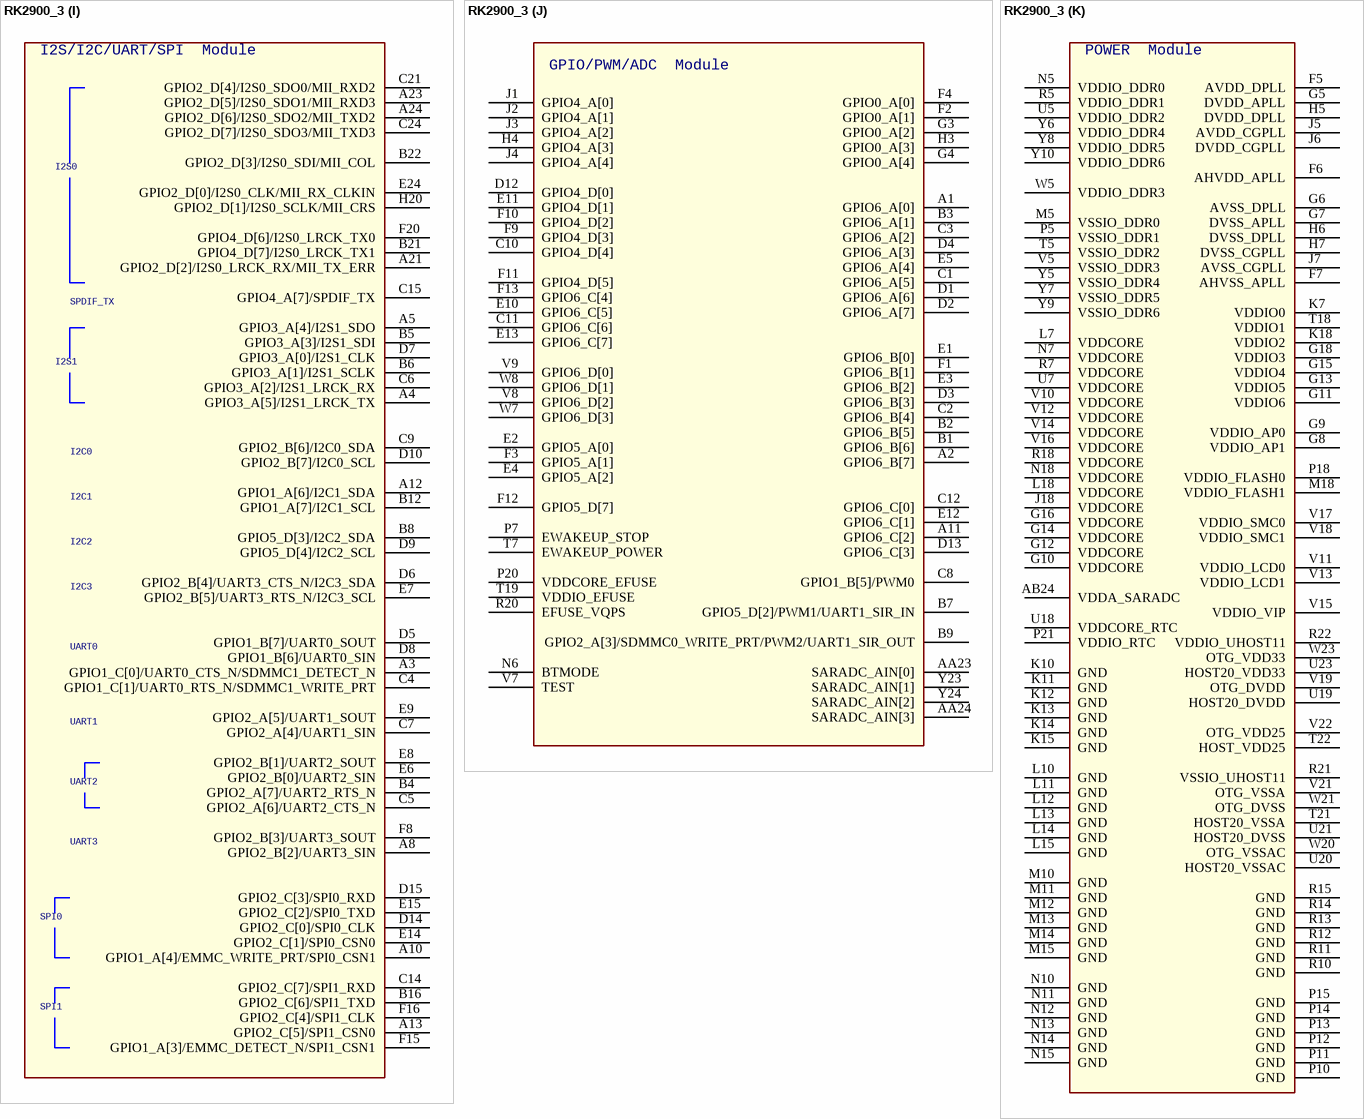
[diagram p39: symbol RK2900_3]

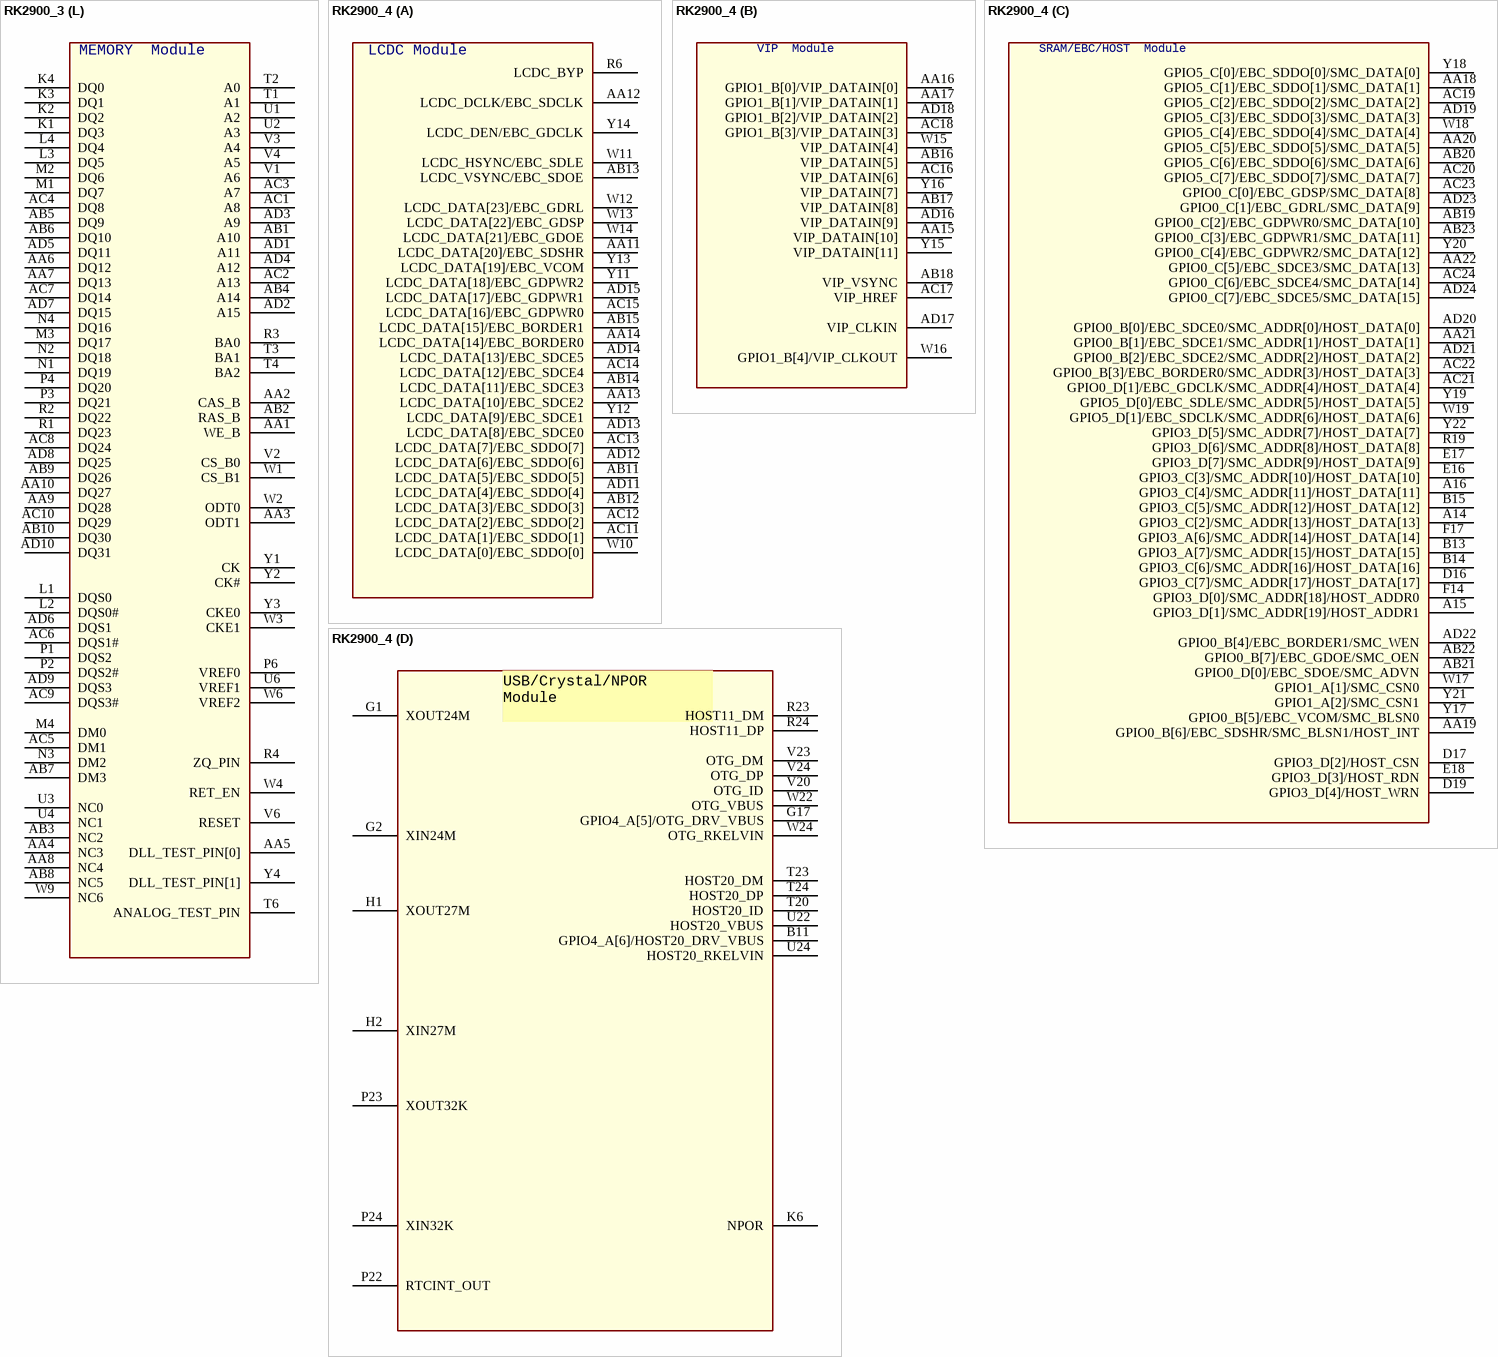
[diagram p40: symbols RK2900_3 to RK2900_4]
